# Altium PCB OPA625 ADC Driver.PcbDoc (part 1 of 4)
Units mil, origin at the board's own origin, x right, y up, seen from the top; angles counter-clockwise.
Board outline 4590 x 3930 mil, 4 copper layers (Layer 1 - Top Layer, Layer 2 - GND, Layer 3 - PWR, Layer 4 - Bottom Layer), stack 59.034 mil thick; 428 components, 236 nets, 1203 pads, 546 vias.
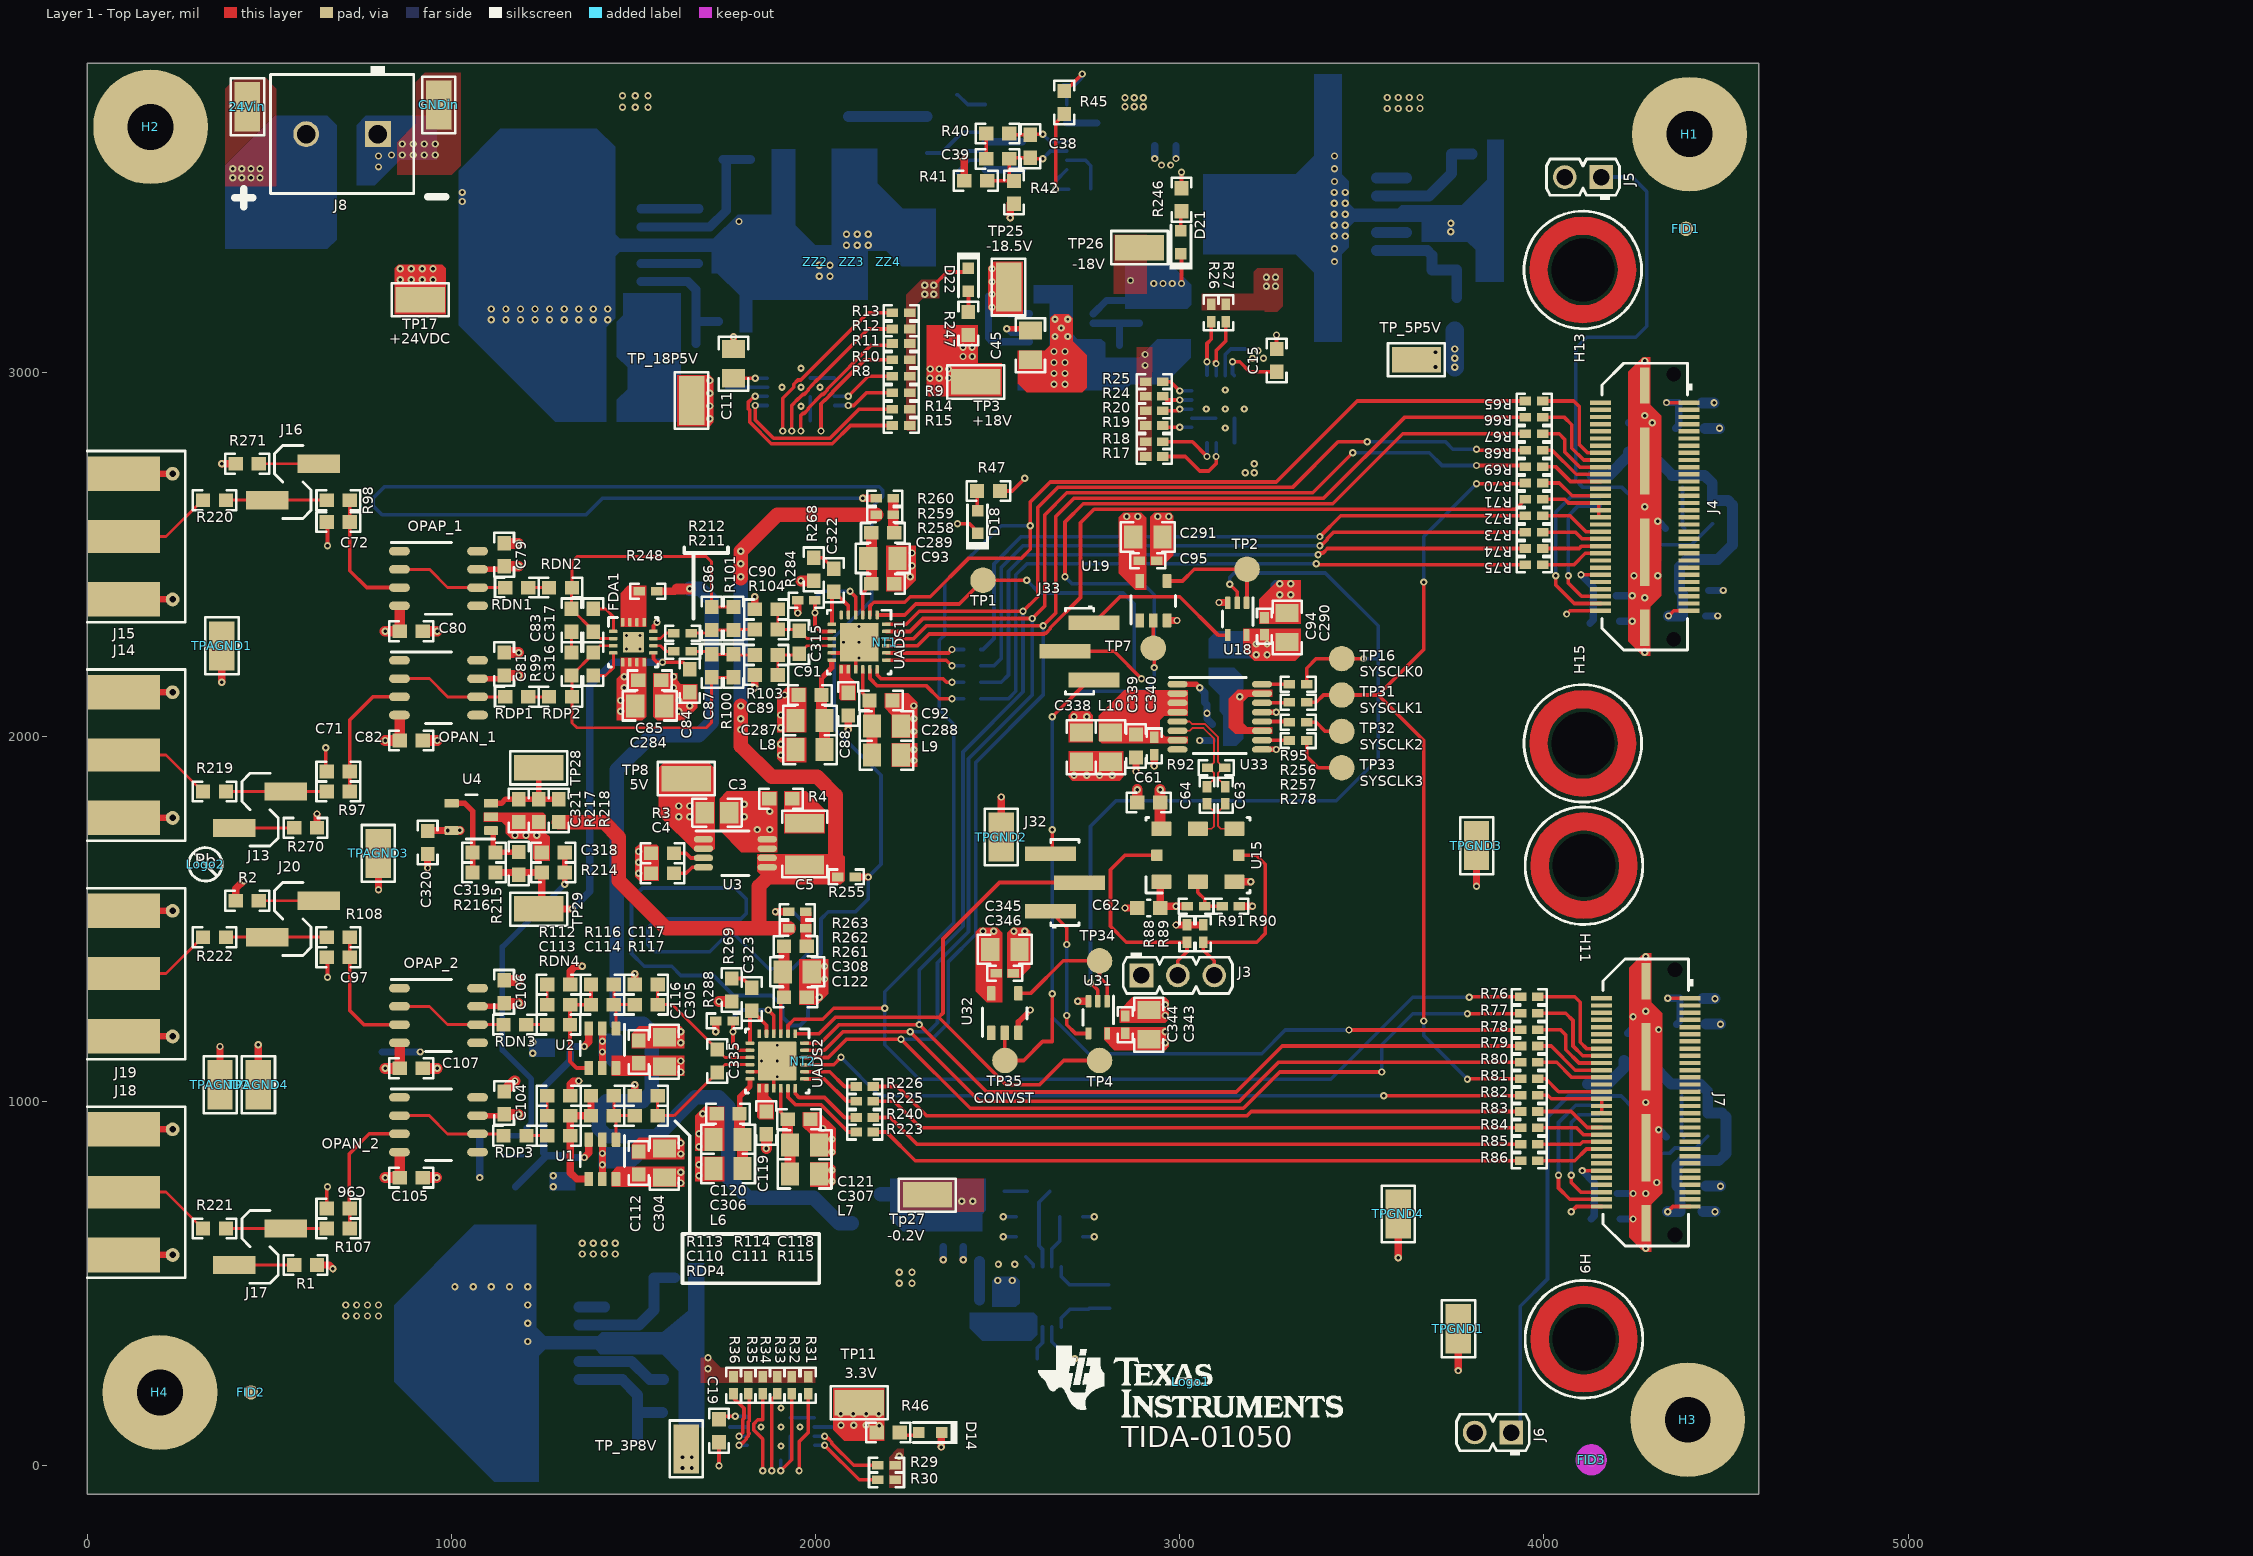
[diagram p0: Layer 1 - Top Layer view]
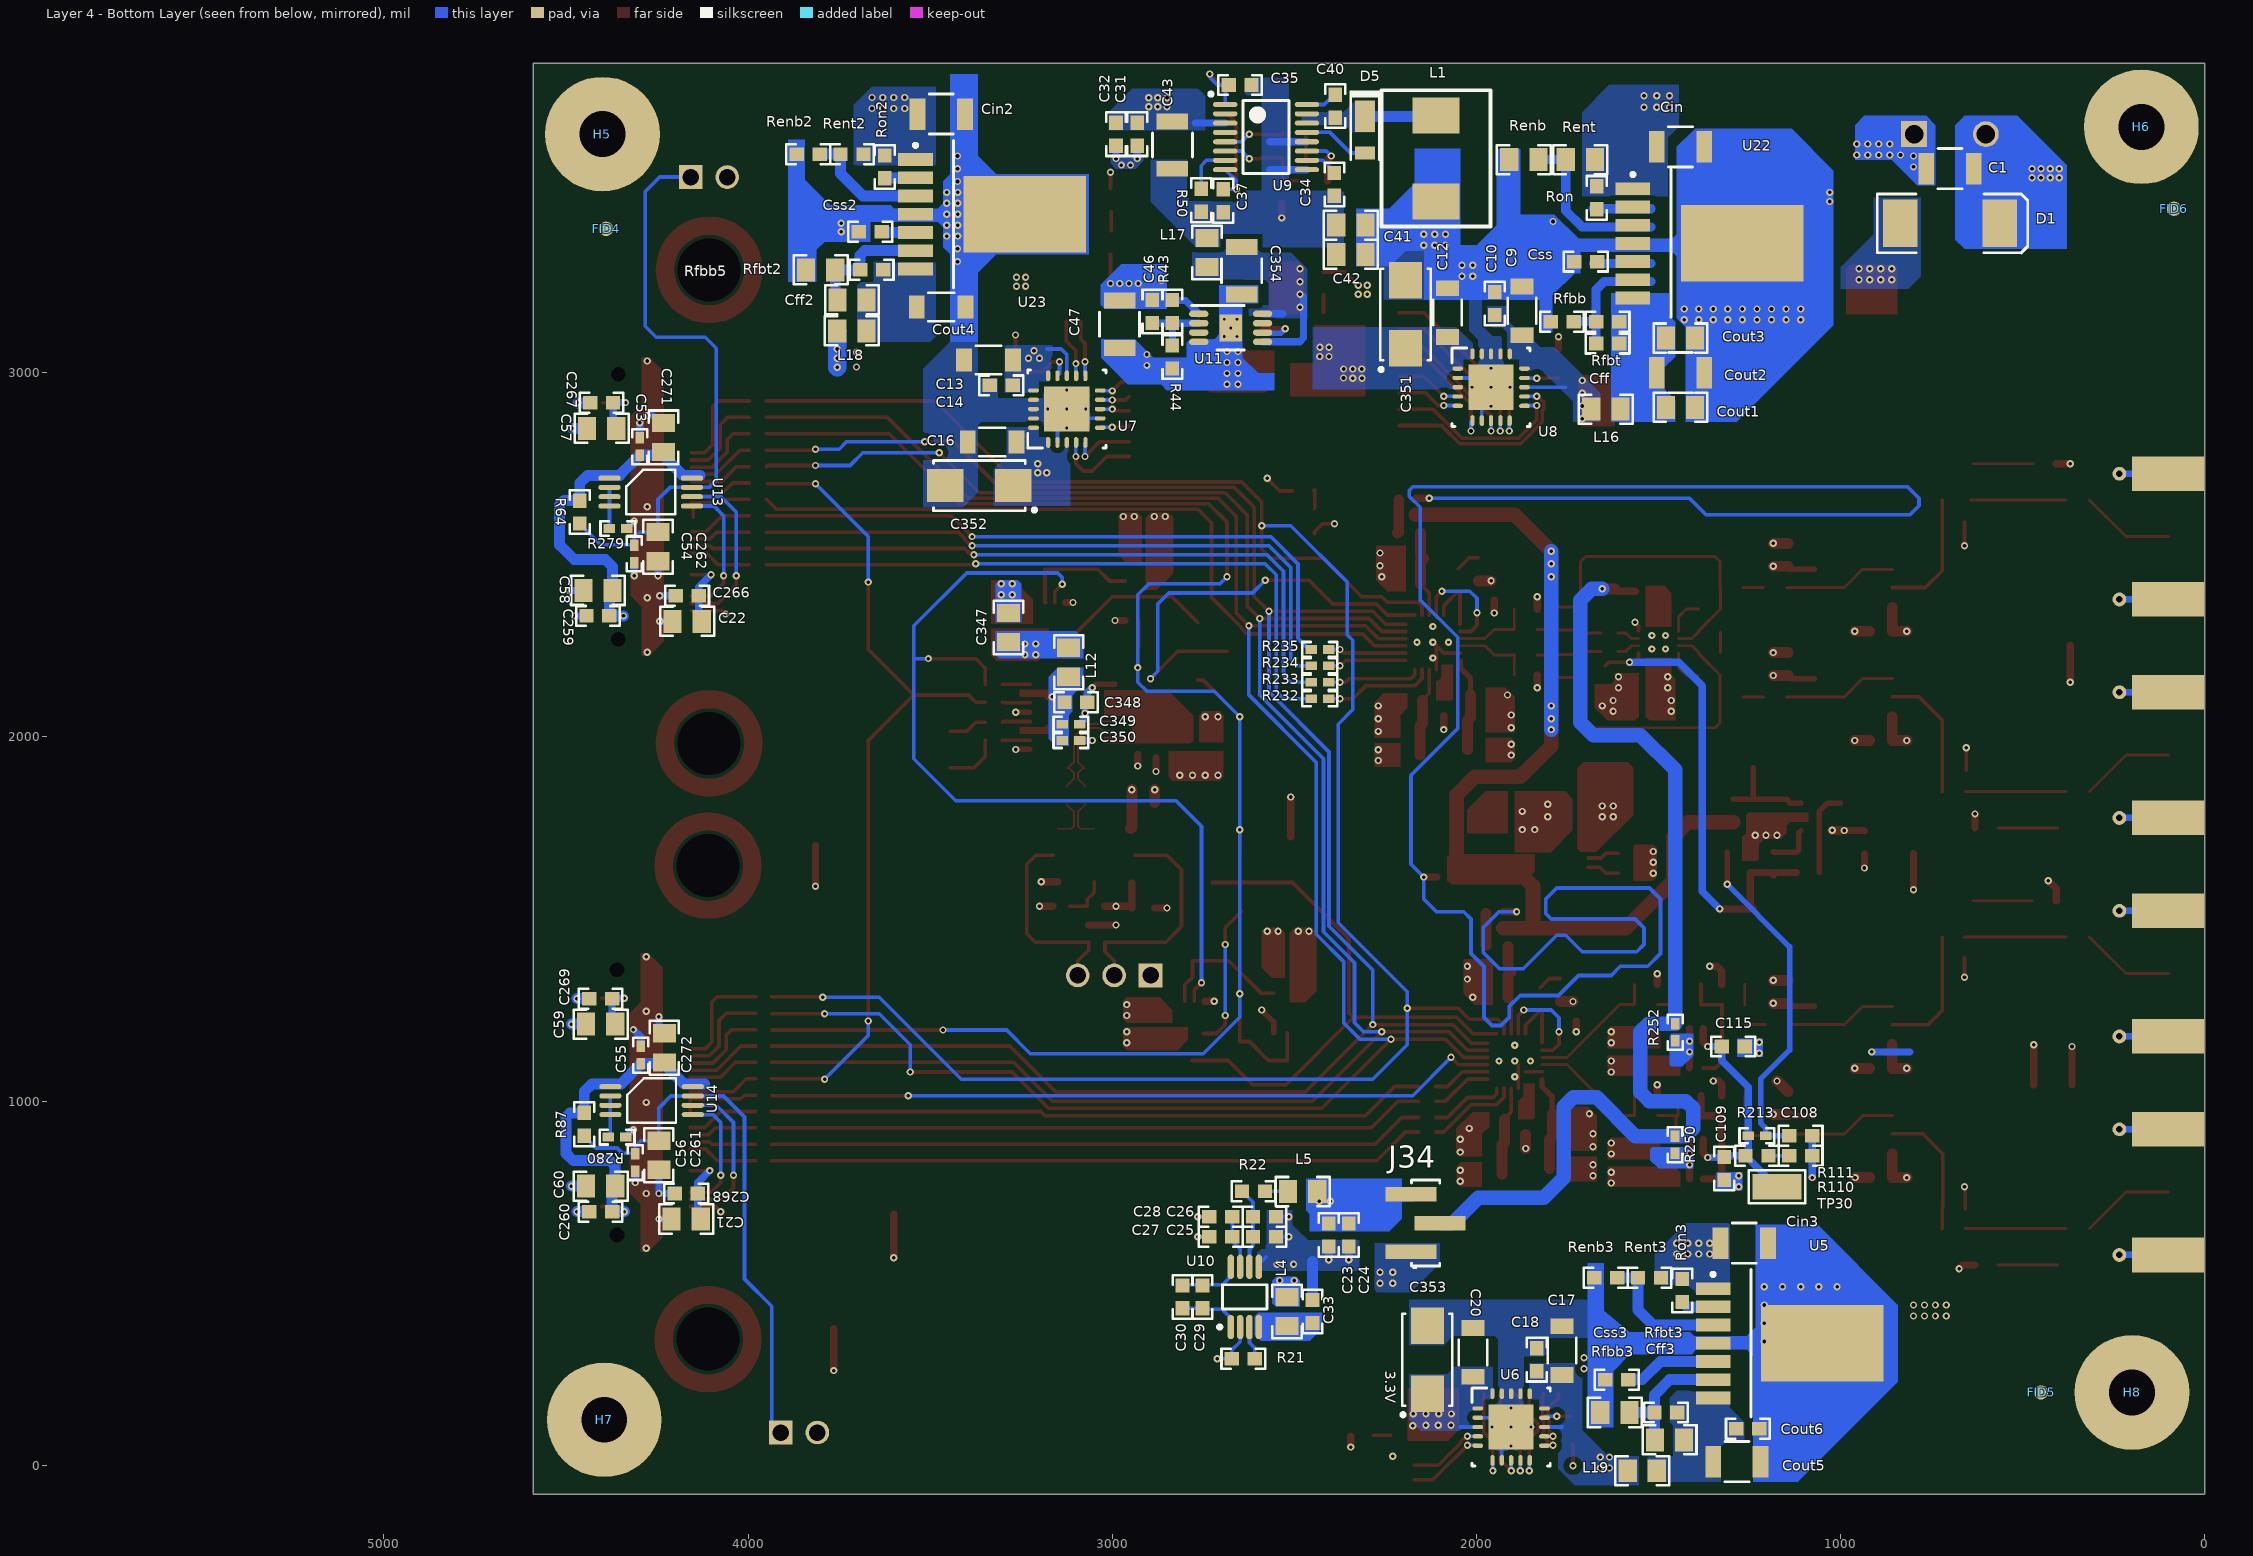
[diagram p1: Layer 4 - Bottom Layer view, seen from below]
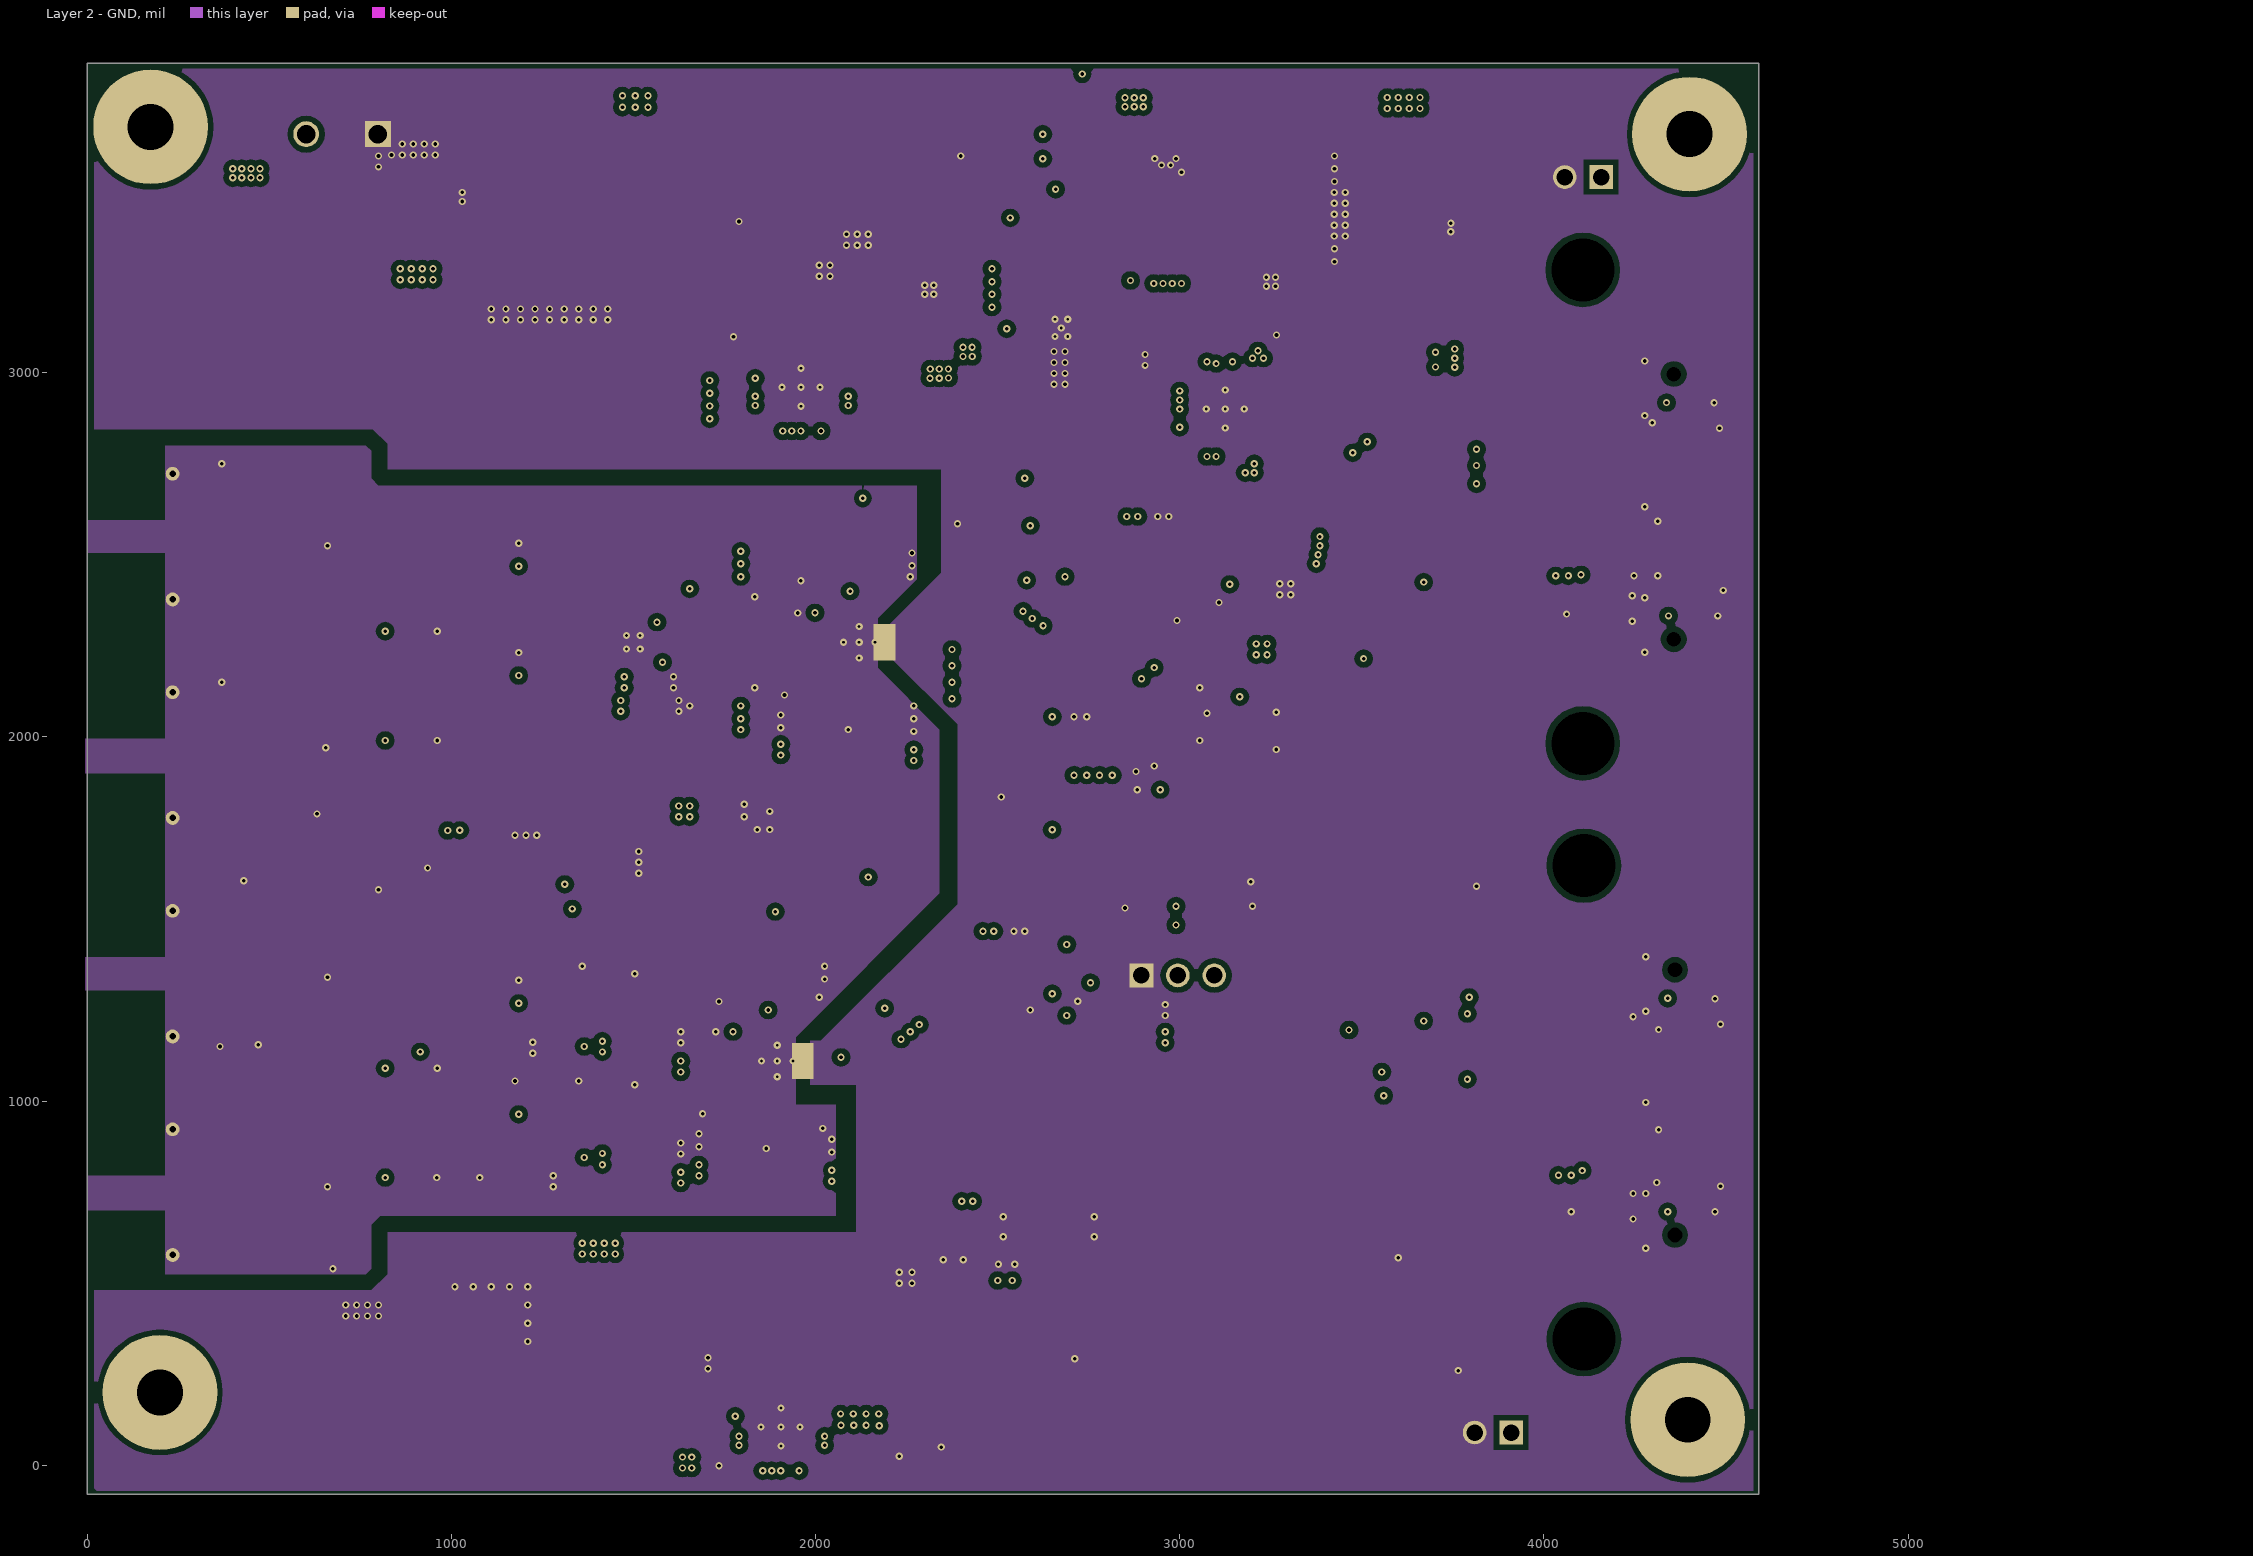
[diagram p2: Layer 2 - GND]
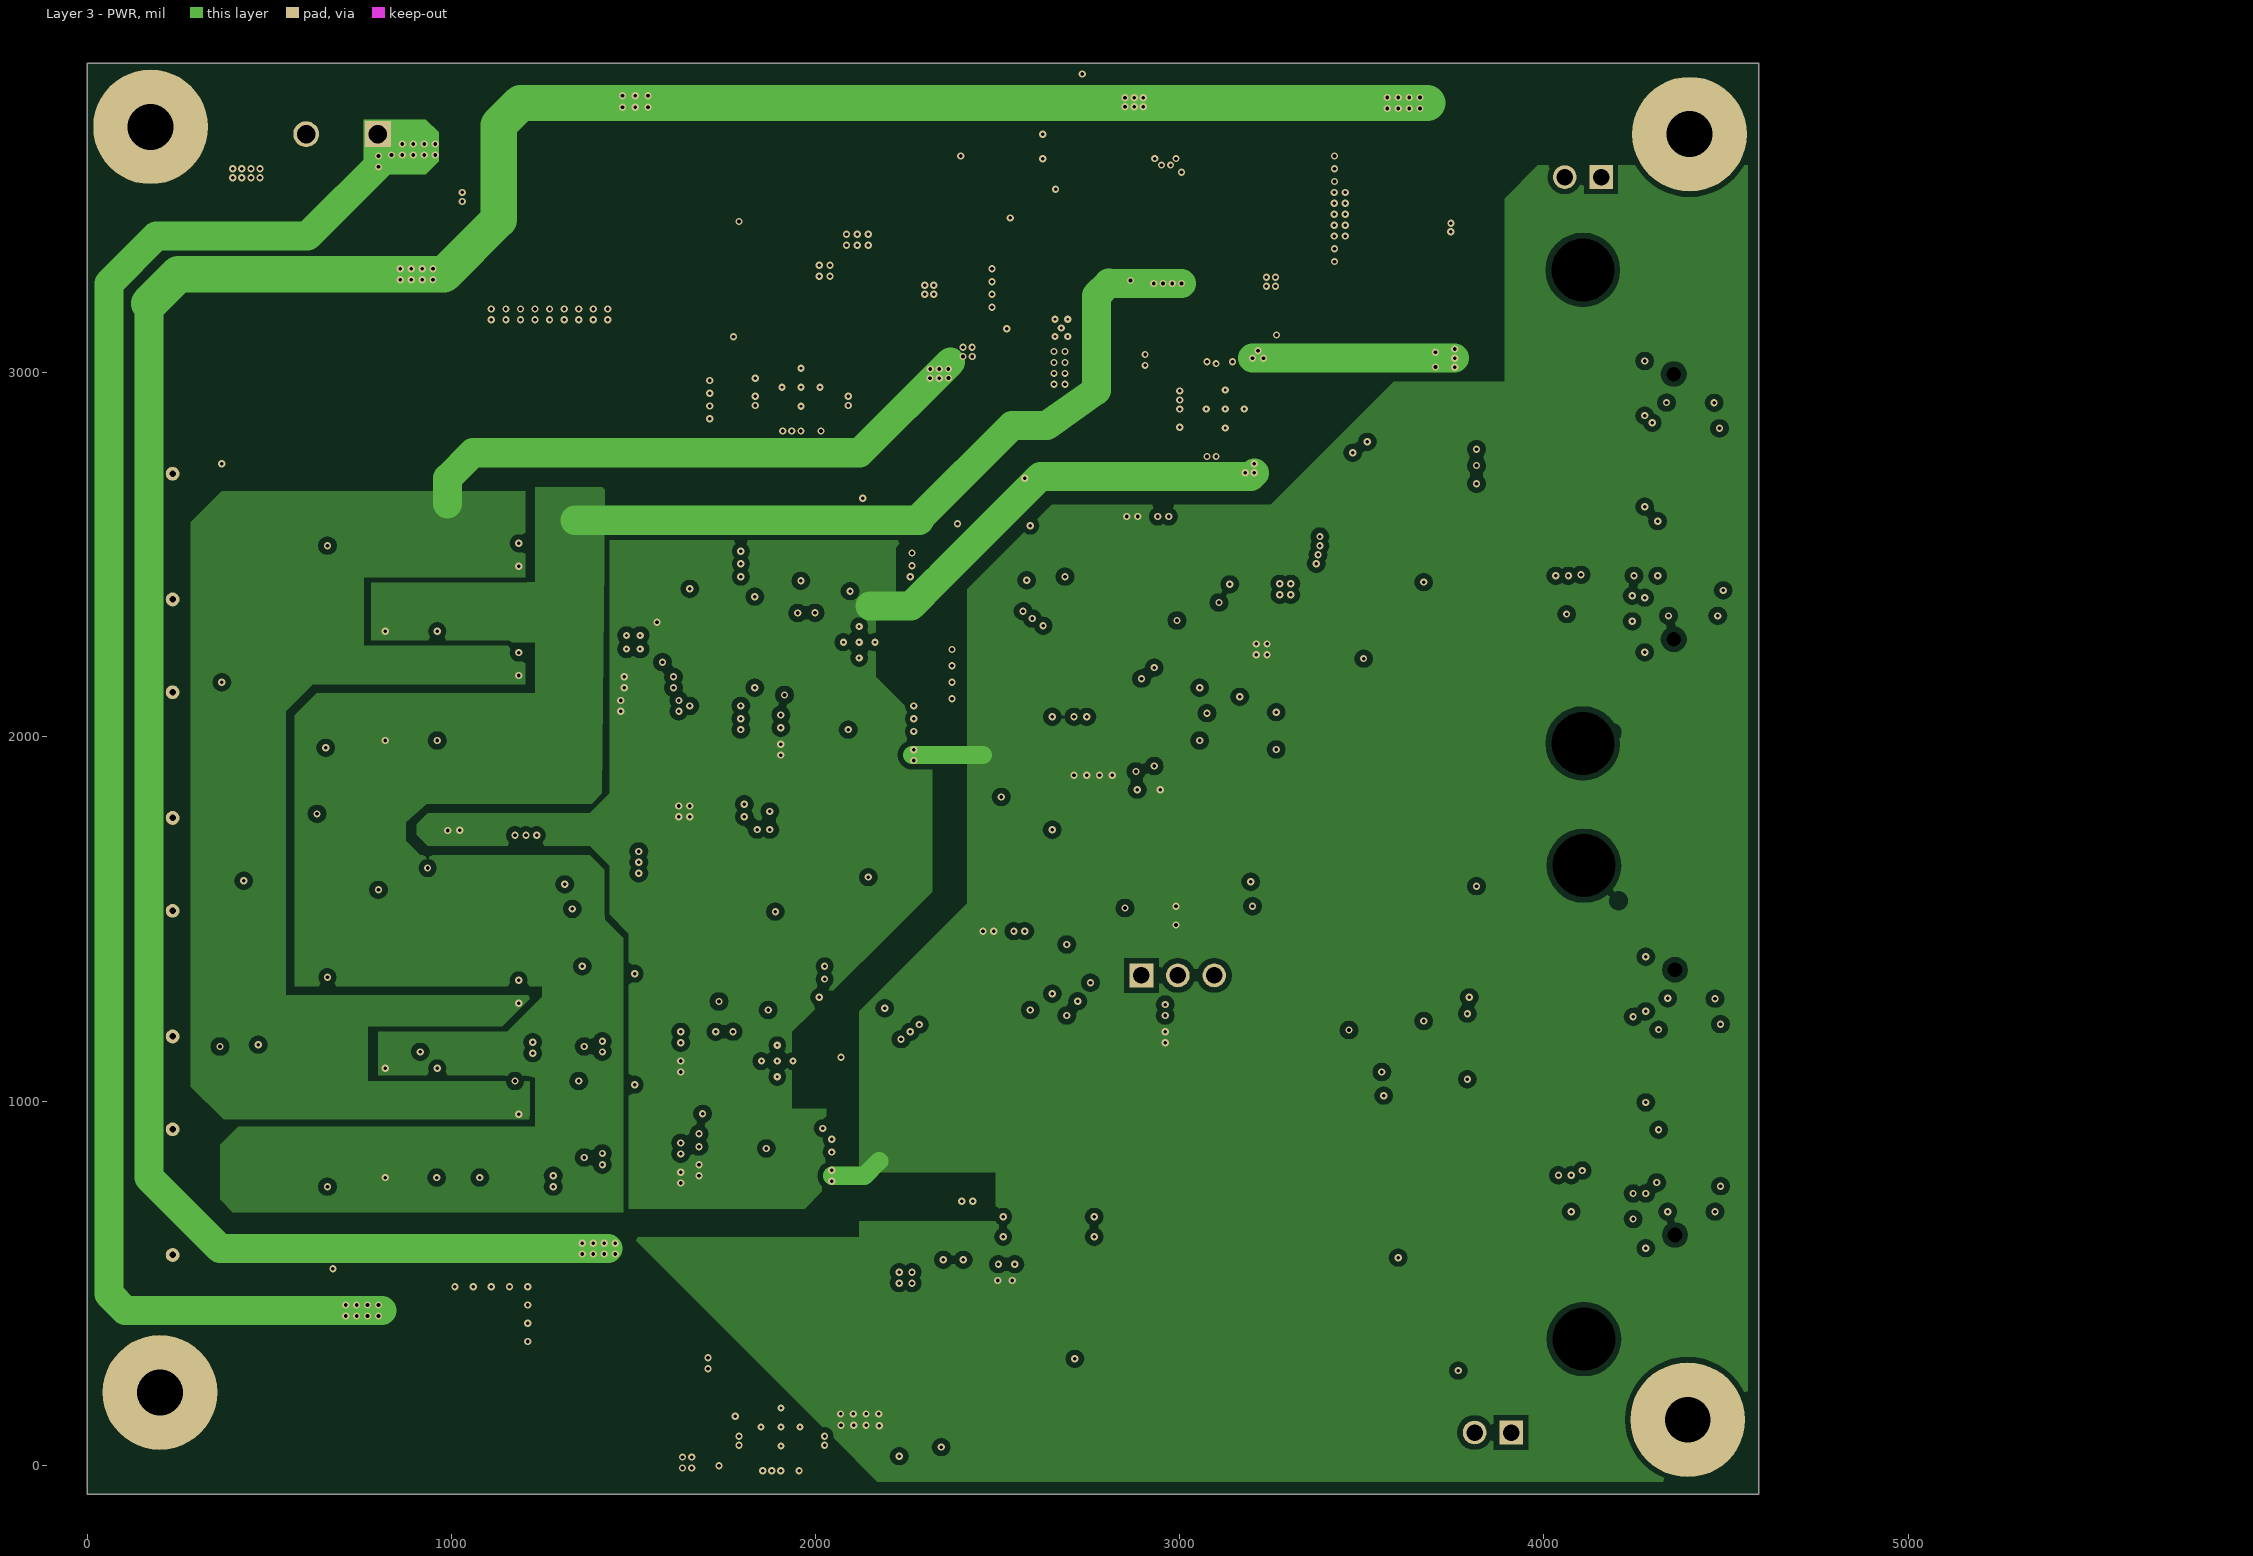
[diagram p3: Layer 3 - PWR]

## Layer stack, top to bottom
Top Solder: solder mask 0.4, Solder Resist, Dk 3.5
Layer 1 - Top Layer: signal copper 1.4
Dielectric 1: prepreg 5.2, 370HR, Dk 4.2
Layer 2 - GND: signal copper 1.417
Dielectric 2: core 43, 370HR, Dk 4.2
Layer 3 - PWR: signal copper 1.417
Dielectric 3: prepreg 5.2, 370HR, Dk 4.2
Layer 4 - Bottom Layer: signal copper 1.4
Bottom Solder: solder mask 0.4, Solder Resist, Dk 3.5

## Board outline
0,-80 0,3850 4590,3850 4590,-80

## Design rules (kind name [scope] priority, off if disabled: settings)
AcuteAngle [All] p1: minimum=4.50000000000000E+0001 checktracksonly=FALSE
AssemblyTestPointUsage [All] p1: valid=2
Clearance Clearance_Keepouts [((IsTrack Or IsArc) And Not InPoly) And IsFree and IsKeepOut vs ((IsTrack Or IsArc) And Not InPoly) And IsFree and IsKeepOut] p1: gap=0
Clearance Clearance_BoardEdge_MountingHoles [OnCopper and InComponentClass('Mounting Holes') vs IsKeepOut] p2: gap=40
Clearance Clearance_BoardEdge_Poly [OnCopper and InPoly vs IsKeepOut] p3: gap=25
Clearance Clearance_BoardEdge [OnCopper and Not InComponentClass('Logo') and not InComponentClass('FiducialMark') and not InRegion(1000,500,4000,800) and Not IsKeepout vs IsKeepOut] p4: gap=75
Clearance Clearance_Poly [InPolygon] p5: gap=15
Clearance [All] p6: gap=5
ComponentClearance ComponentClearance_MountingHoles_FiducialMarks [InComponentClass('Mounting Holes') vs InComponentClass('FiducialMark')] p1: gap=25 collisioncheckmode=3 verticalgap=10 showdistances=FALSE
ComponentClearance ComponentClearance_Shunt [InComponentClass('Header') vs InComponentClass('Shunt')] p2: gap=0 collisioncheckmode=3 verticalgap=0 showdistances=FALSE
ComponentClearance ComponentClearance_Logo [InComponentClass('Logo')] p3: gap=10 collisioncheckmode=3 verticalgap=10 showdistances=FALSE
ComponentClearance ComponentClearance_ScrewToNut [(HasFootprint('NY PMS 440 0025 PH')) vs (HasFootprint('Keystone_1902C'))] p4: gap=5 collisioncheckmode=3 verticalgap=10 showdistances=FALSE
ComponentClearance ComponentClearance_MountingHoles [InComponentClass('Mounting Holes')] p5: gap=15 collisioncheckmode=3 verticalgap=100000 showdistances=FALSE
ComponentClearance ComponentClearance_SmallPassives [HasFootprint('0201*') or HasFootprint('0402*') or HasFootprint('0508') or HasFootprint('0603*') or HasFootprint('0612') or HasFootprint('0805*') or HasFootprint('0815*') or HasFootprint('0830*') or HasFootprint('1206*') or HasFootprint('1210*') or HasFootprint('1808*') or HasFootprint('1812*') or HasFootprint('1825*') or HasFootprint('2010*') or HasFootprint('2220*') or HasFootprint('2225*') or HasFootprint('2512*') or HasFootprint('2728*') or HasFootprint('3518*') vs HasFootprint('0201*') or HasFootprint('0402*') or HasFootprint('0508') or HasFootprint('0603*') or HasFootprint('0612') or HasFootprint('0805*') or HasFootprint('0815*') or HasFootprint('0830*') or HasFootprint('1206*') or HasFootprint('1210*') or HasFootprint('1808*') or HasFootprint('1812*') or HasFootprint('1825*') or HasFootprint('2010*') or HasFootprint('2220*') or HasFootprint('2225*') or HasFootprint('2512*') or HasFootprint('2728*') or HasFootprint('3518*')] p6: gap=5 collisioncheckmode=3 verticalgap=10 showdistances=FALSE
ComponentClearance ComponentClearance_THtoSMT [IsThruComponent vs IsSMTComponent] p7: gap=10 collisioncheckmode=3 verticalgap=30 showdistances=FALSE
ComponentClearance ComponentClearance_THtoTH [IsThruComponent vs IsThruComponent] p8: gap=75 collisioncheckmode=3 verticalgap=30 showdistances=FALSE
ComponentClearance [All] p9: gap=5 collisioncheckmode=3 verticalgap=10 showdistances=FALSE
DiffPairsRouting [All] p1: maxlimit=20 minlimit=6 mostfreqgap=6 toplayer_minwidth=5 toplayer_maxwidth=5 toplayer_prefwidth=5 midlayer1_minwidth=5 midlayer1_maxwidth=5 midlayer1_prefwidth=5 midlayer2_minwidth=5 midlayer2_maxwidth=5 midlayer2_prefwidth=5 bottomlayer_minwidth=5 bottomlayer_maxwidth=5 bottomlayer_prefwidth=5 maxuncoupledlength=1000
FabricationTestPointUsage TestPointUsage [All] p1: valid=2 allowmultiple=FALSE
FabricationTestpoint Testpoint [All] p1: side=3 testpointundercomponent=TRUE minsize=40 maxsize=100 preferedsize=60 minholesize=0 maxholesize=40 preferedholesize=32 testpointgrid=1 allowsidetop=TRUE allowsidebottom=TRUE usegrid=TRUE gridtolerance=0.01
FanoutControl Fanout_LCC [IsLCC] p1: bgadir=Out bgaviamode=Centered fanoutstyle=Auto fanoutdirection=Alternating viagrid=1 // Fanout_LCC (Default Rule)
FanoutControl Fanout_BGA [IsBGA] p2: bgadir=Out bgaviamode=Centered fanoutstyle=Auto fanoutdirection=Alternating viagrid=1 // Fanout_BGA (Default Rule)
FanoutControl Fanout_Default [All] p4: bgadir=Out bgaviamode=Centered fanoutstyle=Auto fanoutdirection=Alternating viagrid=1 // Fanout_Default (Default Rule)
FanoutControl Fanout_Small [(CompPinCount < 5)] p5: bgadir=Out bgaviamode=Centered fanoutstyle=Auto fanoutdirection=OutThenIn viagrid=1 // Fanout_Small (Default Rule)
HoleSize [All] p1: absolutevalues=TRUE maxlimit=251 minlimit=6 maxpercent=80.000 minpercent=20.000
MinimumAnnularRing MinimumAnnularRing_ThermalPadVias [IsVia and InAnyComponent] p1: minimumring=5.91
MinimumAnnularRing [All] p2: minimumring=5
MinimumSolderMaskSliver MinimumSolderMaskSliver_Logo [InComponentClass('Logo') vs InComponentClass('Logo')] p1: minsoldermaskwidth=0.7
MinimumSolderMaskSliver [All] p2: minsoldermaskwidth=3.94
PlaneConnect [All] p1: planeconnectstyle=Relief reliefexpansion=10 reliefentries=4 reliefconductorwidth=10 reliefairgap=10
PolygonConnect [All] p1: connectstyle=Direct reliefconductorwidth=10 reliefentries=4 polygonreliefangle="90 Angle" airgapwidth=10
RoutingVias ThermalPadVias [IsVia and InAnyComponent] p1: holewidth=7.87 width=19.68 viastyle="Through Hole" minholewidth=7.87 minwidth=19.68 maxholewidth=12.99 maxwidth=23.62
RoutingVias [All] p2: holewidth=16 width=34 viastyle="Through Hole" minholewidth=7.87 minwidth=20 maxholewidth=40 maxwidth=65
SilkToBoardRegionClearance [Not ((IsComment or IsDesignator) And (Hide <> 'False')) and not InRegion(1000,500,4000,800)] p1:
SilkToSilkClearance SilkToSilkClearance_Pb-FreeLogo [(HasFootprint('Pb-Free_Overlay_Medium') OR HasFootprint('Pb-Free_Overlay_Small')) vs (HasFootprint('Pb-Free_Overlay_Medium') OR HasFootprint('Pb-Free_Overlay_Small'))] p1: silktosilkclearance=0
SilkToSilkClearance [All] p2: silktosilkclearance=4
SilkToSolderMaskClearance SilkToComonentPadClearance [IsPad and InAnycomponent] p1: minsilkscreentomaskgap=4 clearancetoexposedcopper=TRUE
SilkToSolderMaskClearance "Silk to Solder Mask Opening" [All] p2: minsilkscreentomaskgap=4 clearancetoexposedcopper=FALSE
SolderMaskExpansion [All] p1: expansion=1.97
Width [All] p1: maxlimit=100 minlimit=5 preferedwidth=10 checkconnectedcopper=TRUE
15 further rules are at their usual default settings.

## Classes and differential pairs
component class "OPA625 ADC Driver_Power": 24Vin C1 C9 C10 C11 C12 C13 C14 C15 C16 C17 C18 C19 C20 C23 C24 C25 C26 C27 C28 C29 C30 C31 C32 C33 C34 C35 C37 C38 C39 C40 C41 C42 C43 C45 C46 C47 C351 C352 C353 C354 Cff Cff2 Cff3 Cin Cin2 Cin3 Cout1 Cout2 Cout3 Cout4 Cout5 Cout6 Css Css2 Css3 D1 D5 D14 D18 D21 D22 GNDin J8 J34 L1 L4 L5 L16 L17 L18 L19 NT1 NT2 R8 R9 R10 R11 R12 R13 R14 R15 R17 R18 R19 R20 R21 R22 R24 R25 R26 R27 R29 R30 R31 R32 R33 R34 R35 R36 R40 R41 R42 R43 R44 R45 R46 R47 R50 R246 R247 Renb Renb2 Renb3 Rent Rent2 Rent3 Rfbb Rfbb3 Rfbb5 Rfbt Rfbt2 Rfbt3 Ron Ron2 Ron3 TP3 TP8 TP11 TP17 TP25 TP26 Tp27 TP_3P8V TP_5P5V TP_18P5V TPAGND1 TPAGND2 TPAGND3 TPAGND4 TPGND TPGND1 TPGND2 TPGND3 TPGND4 U5 U6 U7 U8 U9 U10 U11 U22 U23
component class "OPA625 ADC Driver_OPA625 ADC Driver": C3 C4 C5 C71 C72 C79 C80 C81 C82 C83 C84 C85 C86 C87 C88 C89 C90 C91 C92 C93 C94 C95 C96 C97 C104 C105 C106 C107 C108 C109 C110 C111 C112 C113 C114 C115 C116 C117 C118 C119 C120 C121 C122 C284 C287 C288 C289 C290 C291 C304 C305 C306 C307 C308 C315 C316 C317 C318 C319 C320 C321 C322 C323 C335 C343 C344 C345 C346 FDA1 J13 J14 J15 J16 J17 J18 J19 J20 J32 J33 L6 L7 L8 L9 OPAN_1 OPAN_2 OPAP_1 OPAP_2 R1 R2 R3 R4 R97 R98 R99 R100 R101 R103 R104 R107 R108 R110 R111 R112 R113 R114 R115 R116 R117 R211 R212 R213 R214 R215 R216 R217 R218 R219 R220 R221 R222 R223 R225 R226 R232 R233 R234 R235 R240 R248 R250 R252 R255 R258 R259 R260 R261 R262 R263 R268 R269 R270 R271 R284 R288 RDN1 RDN2 RDN3 RDN4 RDP1 RDP2 RDP3 RDP4 TP1 Tp2 TP4 TP7 TP28 TP29 TP30 TP34 TP35 U1 U2 U3 U4 U18 U19 U31 U32 UADS1 UADS2
component class "OPA625 ADC Driver_Connectors": C21 C22 C53 C54 C55 C56 C57 C58 C59 C60 C259 C260 C261 C262 C266 C267 C268 C269 C271 C272 J4 J5 J6 J7 R64 R65 R66 R67 R68 R69 R70 R71 R72 R73 R74 R75 R76 R77 R78 R79 R80 R81 R82 R83 R84 R85 R86 R87 R279 R280 U13 U14
component class "OPA625 ADC Driver_Clock": C61 C62 C63 C64 C338 C339 C340 C347 C348 C349 C350 J3 L10 L12 R88 R89 R90 R91 R92 R95 R256 R257 R278 TP16 TP31 TP32 TP33 U15 U33
component class Header: J3 J5 J6 J13 J16 J17 J20 J32 J33 J34
component class "Mounting Holes": H1 H2 H3 H4
component class Logo: Logo1
component class "OPA625 ADC Driver_Hardware": FID1 FID2 FID3 FID4 FID5 FID6 H1 H2 H3 H4 H5 H6 H7 H8 H9 H11 H13 H15 Logo1 Logo2 ZZ2 ZZ3 ZZ4
component class FiducialMark: FID1 FID2 FID3 FID4 FID5 FID6
component class AssemblyNote: ZZ2 ZZ3 ZZ4
differential pair BCLK1: +BCLK1_P -BCLK1_N
differential pair BCLK0: +BCLK0_P -BCLK0_N

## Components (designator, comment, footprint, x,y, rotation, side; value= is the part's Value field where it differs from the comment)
24Vin "5015" Testpoint_Keystone_Miniature 440,3730 r90 top
C1 "UMK325AB7106KM-T" 1210_280 700,3560 r0 bottom
C3 "GRM21BR71A106KE51L" 0805 1729.79,1791.91 r180 top
C4 "GRM188R71A105KA61D" 0603 1580,1625.41 r180 top
C5 "GRM32ER71A476KE15L" 1210_270 1970,1705.41 r90 top
C9 "C3216X5R1E476M160AC" 1206_190 1875,3170 r90 bottom
C10 "CGA3E2X7R2A102K080AA" 0603 1950,3190 r90 bottom
C11 "C2012X7S2A105K125AB" 0805_HV 1775,3025 r90 top
C12 "C3216X5R1E476M160AC" 1206_190 2080,3165 r90 bottom
C13 "C3216X5R1E476M160AC" 1206_190 3340,3035 r0 bottom
C14 "GRM1885C1H102FA01J" 0603 3305,2965 r0 bottom
C15 "GRM188R71E105KA12D" 0603 3266.02,3033.66 r270 top
C16 "C3216X5R1E476M160AC" 1206_190 3330,2810 r0 bottom
C17 "C3216X5R1E476M160AC" 1206_190 1765,315 r90 bottom
C18 "GRM1885C1H102FA01J" 0603 1835,290 r90 bottom
C19 "GRM188R71E105KA12D" 0603 1735,95 r90 top
C20 "C3216X5R1E476M160AC" 1206_190 2010,310 r90 bottom
C21 "GRM21BR71A106KE51L" 0805_HV 4169.99,676.32 r0 bottom
C22 "GRM21BR71A106KE51L" 0805_HV 4167.34,2317.19 r0 bottom
C23 "GRM188R61A106ME69D" 0603 2406.02,632.23 r270 bottom
C24 "GRM188R61A106ME69D" 0603 2351.02,632.23 r270 bottom
C25 "GRM188R71E474KA12D" 0603 2582.25,627.23 r180 bottom
C26 "GRM188R60J226MEA0D" 0603 2582.25,682.23 r180 bottom
C27 "GRM188R61C104KA01D" 0603 2702.25,627.23 r0 bottom
C28 "GRM188R60J226MEA0D" 0603 2702.25,682.23 r0 bottom
C29 "GRM188R61A475MAAJ" 0603 2752.25,462.23 r90 bottom
C30 "GRM188R61A224KA01D" 0603 2807.25,462.23 r90 bottom
C31 "GCM188R71H224KA64D" 0603 2931.46,3655 r270 bottom
C32 "C1608X7R1H104K080AA" 0603 2990,3655 r270 bottom
C33 "GRM188R61A106ME69D" 0603 2450.2,422.23 r90 bottom
C34 "GRM188R71H333KA61D" 0603 2390.15,3516.89 r270 bottom
C35 "C1608X7R1H104K080AA" 0603 2649.25,3789.94 r180 bottom
C37 "C0603C911J5GACTU" 0603 2695.15,3471.89 r270 bottom
C38 "CGA3E2C0G1H100D080AA" 0603 2590.15,3621.89 r90 top
C39 "GRM1885C1H151JA01D" 0603 2500.15,3586.89 r180 top
C40 "GRM188R71H223KA01D" 0603 2387.87,3731.89 r90 bottom
C41 "C2012X5R1V226M125AC" 0805_HV 2345,3405 r0 bottom
C42 "C2012X7S2A105K125AB" 0805_HV 2345,3325 r0 bottom
C43 "UMK325AB7106KM-T" 1210_280 2835,3625 r270 bottom
C45 "C2012X7S2A105K125AB" 0805_HV 2590.21,3075.7 r270 top
C46 "GCM188R71H103KA37D" 0603 2890,3168.05 r270 bottom
C47 "UMK325AB7106KM-T" 1210_280 2980,3133.05 r270 bottom
C53 "GRM155R71C104KA88D" 0402 4297.34,2797.19 r270 bottom
C54 "GRM155R71C104KA88D" 0402 4312.34,2502.19 r90 bottom
C55 "GRM155R71C104KA88D" 0402 4294.99,1126.32 r270 bottom
C56 "GRM155R71C104KA88D" 0402 4310,831.32 r90 bottom
C57 "GRM21BR71A106KE51L" 0805_HV 4402.34,2847.19 r0 bottom
C58 "GRM21BR71A106KE51L" 0805_HV 4412.34,2402.19 r0 bottom
C59 "GRM21BR71A106KE51L" 0805_HV 4405,1211.32 r0 bottom
C60 "GRM21BR71A106KE51L" 0805_HV 4405,766.32 r0 bottom
C61 "C0603C104J3RACTU" 0603 2915,1820 r180 top
C62 "ZRB18AD71A106KE01L" 0603_120 2915,1530 r180 top
C63 "GRM155R61E104KA87D" 0402 3125,1840 r90 top
C64 "GRM155R61E104KA87D" 0402 3075,1840 r90 top
C71 "GRM1885C1H101JA01D" 0603 690,1905 r0 top
C72 "GRM1885C1H101JA01D" 0603 690,2590 r0 top
C79 "GRM188R72A104KA35D" 0603 1145,2500 r270 top
C80 "GRM188R72A104KA35D" 0603 890,2290 r180 top
C81 "GRM188R72A104KA35D" 0603 1145,2200 r270 top
C82 "GRM188R72A104KA35D" 0603 889.99,1990 r180 top
C83 "C0603C680J5GACTU" 0603 1330,2320 r90 top
C84 "C0603C104J3RACTU" 0603 1655,2154 r270 top
C85 "C0603C104J3RACTU" 0603 1545,2155 r0 top
C86 "C0603C270J5GACTU" 0603 1715,2325 r90 top
C87 "C0603C270J5GACTU" 0603 1715,2195 r270 top
C88 "GRM188R71A105KA61D" 0603 2090,2090 r90 top
C89 "C1608C0G2A102J080AA" 0603 1865,2170 r180 top
C90 "C1608C0G2A102J080AA" 0603 1865,2350 r180 top
C91 "C0603C104J3RACTU" 0603 1985,2115 r0 top
C92 "C0603C104J3RACTU" 0603 2180,2100 r0 top
C93 "C0603C104J3RACTU" 0603 2185,2420 r0 top
C94 "GRM155R71C104KA88D" 0402 3232.81,2303.8 r270 top
C95 "GRM155R71C104KA88D" 0402 2912.81,2483.8 r180 top
C96 "GRM1885C1H101JA01D" 0603 690,705 r0 top
C97 "GRM1885C1H101JA01D" 0603 690,1395 r0 top
C104 "GRM188R72A104KA35D" 0603 1145,995 r270 top
C105 "GRM188R72A104KA35D" 0603 890,790 r180 top
C106 "GRM188R72A104KA35D" 0603 1145,1300 r270 top
C107 "GRM188R72A104KA35D" 0603 890,1090 r180 top
C108 "C0603C104J3RACTU" 0603 1110,905 r180 bottom
C109 "C0603C102J5GAC" 0603 1320,815 r270 bottom
C110 "C0603C471K5RACTU" 0603 1295,960 r0 top
C111 "C0603C101J5GAC" 0603 1415,960 r180 top
C112 "C0603C104J3RACTU" 0603 1515,830 r270 top
C113 "C0603C471K5RACTU" 0603 1295,1265 r180 top
C114 "C0603C101J5GAC" 0603 1415,1265 r180 top
C115 "C0603C102J5GAC" 0603 1295,1150 r180 bottom
C116 "C0603C104J3RACTU" 0603 1515,1135 r270 top
C117 "C1608C0G2A102J080AA" 0603 1535,1320 r180 top
C118 "C1608C0G2A102J080AA" 0603 1535,1015 r180 top
C119 "GRM188R71A105KA61D" 0603 1865,940 r270 top
C120 "C0603C104J3RACTU" 0603 1760,965 r0 top
C121 "C0603C104J3RACTU" 0603 1955,950 r0 top
C122 "C0603C104J3RACTU" 0603 1945,1285 r0 top
C259 "C0603C104J3RACTU" 0603 4412.34,2332.19 r0 bottom
C260 "C0603C104J3RACTU" 0603 4405,696.32 r0 bottom
C261 "GRM21BR71A106KE51L" 0805_HV 4244.99,851.32 r270 bottom
C262 "GRM21BR71A106KE51L" 0805_HV 4247.34,2522.19 r270 bottom
C266 "C0603C104J3RACTU" 0603 4167.34,2387.19 r0 bottom
C267 "C0603C104J3RACTU" 0603 4402.34,2917.19 r0 bottom
C268 "C0603C104J3RACTU" 0603 4169.99,746.32 r0 bottom
C269 "C0603C104J3RACTU" 0603 4405,1281.33 r0 bottom
C271 "GRM21BR71A106KE51L" 0805_HV 4232.34,2822.19 r90 bottom
C272 "GRM21BR71A106KE51L" 0805_HV 4229.99,1146.32 r90 bottom
C284 "GRM21BR71A106KE51L" 0805_HV 1545,2085 r0 top
C287 "GRM21BR71A106KE51L" 0805_HV 1985,2045 r180 top
C288 "GRM21BR71A106KE51L" 0805_HV 2195,2030 r0 top
C289 "GRM21BR71A106KE51L" 0805_HV 2185,2490 r0 top
C290 "GRM21BR71A106KE51L" 0805_HV 3295,2300.3 r90 top
C291 "GRM21BR71A106KE51L" 0805_HV 2912.81,2548.8 r180 top
C304 "GRM21BR71A106KE51L" 0805_HV 1585,830 r90 top
C305 "GRM21BR71A106KE51L" 0805_HV 1585,1135 r90 top
C306 "GRM21BR71A106KE51L" 0805_HV 1760,895 r180 top
C307 "GRM21BR71A106KE51L" 0805_HV 1970,880 r0 top
C308 "GRM21BR71A106KE51L" 0805_HV 1950,1355 r0 top
C315 "CGA3E2C0G1H103J080AA" 0603 1955,2260 r90 top
C316 "C0603C104J3RACTU" 0603 1390,2200 r90 top
C317 "C0603C104J3RACTU" 0603 1390,2320 r270 top
C318 "GRM188R71E105KA12D" 0603 1280,1682.63 r180 top
C319 "GRM188R71E105KA12D" 0603 1090,1682.63 r180 top
C320 "C0603C104J3RACTU" 0603 935,1710 r90 top
C321 "GRM188R71E105KA12D" 0603 1185,1797.63 r270 top
C322 "C1608X5R1A226M080AC" 0603 2050,2430 r90 top
C323 "C1608X5R1A226M080AC" 0603 1825,1280 r90 top
C335 "CGA3E2C0G1H103J080AA" 0603 1730,1110 r90 top
C338 "GRM21BR71A106KE51L" 0805_HV 2730,1971.91 r90 top
C339 "GRM188R71E105KA12D" 0603 2880,1975 r270 top
C340 "GRM155R71C104KA88D" 0402 2930,1975 r270 top
C343 "GRM21BR71A106KE51L" 0805_HV 2915.21,1210 r90 top
C344 "GRM155R71C104KA88D" 0402 2850.21,1210 r270 top
C345 "GRM21BR71A106KE51L" 0805_HV 2519.83,1416.53 r180 top
C346 "GRM155R71C104KA88D" 0402 2519.83,1351.53 r180 top
C347 "GRM21BR71A106KE51L" 0805_HV 3285,2300.3 r90 bottom
C348 "GRM188R71E105KA12D" 0603 3100,2095 r180 bottom
C349 "GRM155R71C104KA88D" 0402 3113.55,2035 r180 bottom
C350 "GRM155R71C104KA88D" 0402 3113.55,1990 r180 bottom
C351 "293D475X9025C2TE3" 6032-28 2195,3160 r90 bottom
C352 "293D475X9025C2TE3" 6032-28 3365,2690 r0 bottom
C353 "293D475X9025C2TE3" 6032-28 2135,290 r90 bottom
C354 "UMK325AB7106KM-T" 1210_280 2645,3280 r270 bottom
Cff "C1608X7R2A223K080AA" 0603 1640,3080 r0 bottom
Cff2 "08055C223KAT2A" 0805_HV 3714.76,3200 r0 bottom
Cff3 "08055C223KAT2A" 0805_HV 1470,70 r0 bottom
Cin "UMK325AB7106KM-T" 1210_280 1440,3620 r180 bottom
Cin2 "UMK325AB7106KM-T" 1210_280 3469.76,3710 r180 bottom
Cin3 "UMK325AB7106KM-T" 1210_280 1265,610 r180 bottom
Cout1 "C2012JB1V226M125AC" 0805_HV 1440,2905 r180 bottom
Cout2 "UMK325AB7106KM-T" 1210_280 1440,3000 r180 bottom
Cout3 "C2012X7S2A105K125AB" 0805_HV 1440,3095 r180 bottom
Cout4 "C3216X5R1E476M160AC" 1206_190 3469.76,3180 r180 bottom
Cout5 "C3225X6S0J107M250AC" 1210_280 1285,10 r180 bottom
Cout6 "C0603C105K3RACTU" 0603 1255,100 r180 bottom
Css "CGA3E2X7R2A472K080AA" 0603 1700,3305 r180 bottom
Css2 "GRM188R70J103KA01D" 0603 3664.76,3387 r0 bottom
Css3 "GRM188R70J103KA01D" 0603 1615,235.07 r0 bottom
D1 "MBRS4201T3G" SMC 700,3410 r0 bottom
D5 "DFLS1100-7" PowerDI123 2306.17,3653.35 r270 bottom
D14 "150060RS75000" WL-SMCW_RED 2315,90 r180 top
D18 "150060RS75000" WL-SMCW_RED 2445,2590 r90 top
D21 "150060RS75000" WL-SMCW_RED 3003.32,3358.24 r90 top
D22 "150060RS75000" WL-SMCW_RED 2420,3255 r270 top
FDA1 "THS4551IRGTR" RGT0016A 1500,2260 r0 top
FID1 "Fiducial" Fiducial10-20#1 4390,3395 r90 top
FID2 "Fiducial" Fiducial10-20#1 450,200 r0 top
FID3 "Fiducial" Fiducial10-20#2 4130,15 r90 top
FID4 "Fiducial" Fiducial10-20#1 4390,3395 r270 bottom
FID5 "Fiducial" Fiducial10-20#1 450,200 r180 bottom
FID6 "Fiducial" Fiducial10-20#1 85,3450 r180 bottom
GNDin "5015" Testpoint_Keystone_Miniature 965,3735 r90 top
H1 "NY PMS 440 0025 PH" "NY PMS 440 0025 PH" 4400,3655 r0 top locked
H2 "NY PMS 440 0025 PH" "NY PMS 440 0025 PH" 174.47,3675 r0 top locked
H3 "NY PMS 440 0025 PH" "NY PMS 440 0025 PH" 4395,125 r0 top locked
H4 "NY PMS 440 0025 PH" "NY PMS 440 0025 PH" 200,200 r0 top locked
H5 "1902C" Keystone_1902C 4400,3655 r180 bottom locked
H6 "1902C" Keystone_1902C 174.47,3675 r180 bottom locked
H7 "1902C" Keystone_1902C 4395,125 r180 bottom locked
H8 "1902C" Keystone_1902C 200,200 r180 bottom locked
H9 "9774050360R" Wurth_WA-SMSI 4110,346.32 r180 top
H11 "9774050360R" Wurth_WA-SMSI 4110,1646.32 r180 top
H13 "9774050360R" Wurth_WA-SMSI 4106.85,3282.18 r180 top
H15 "9774050360R" Wurth_WA-SMSI 4106.85,1982.18 r180 top
J3 "61300311121" WURTH_61300311121 2995,1345 r0 top
J4 "QTH-030-01-L-D-A" Samtec_QTH-030-01-x-D-A 4276.85,2632.18 r270 top
J5 "61300211121" WURTH_61300211121 4107.34,3537.19 r180 top
J6 "61300211121" WURTH_61300211121 3860,90 r180 top
J7 "QTH-030-01-L-D-A" Samtec_QTH-030-01-x-D-A 4280,996.32 r270 top
J8 "691213710002" Wurth_691213710002 700,3655 r180 top
J13 "87898-0204" Molex_87898-0204 475,1800 r90 top
J14 "142-0701-801" JOHNSON_142-0701-801 100,1950 r90 top
J15 "142-0701-801" JOHNSON_142-0701-801 100,2550 r90 top
J16 "87898-0204" Molex_87898-0204 565,2700 r270 top
J17 "87898-0204" Molex_87898-0204 475,600 r90 top
J18 "142-0701-801" JOHNSON_142-0701-801 100,750 r90 top
J19 "142-0701-801" JOHNSON_142-0701-801 100,1350 r90 top
J20 "87898-0204" Molex_87898-0204 565,1500 r270 top
J32 "TMM-103-01-G-S-SM" Samtec_TMM-103-01-x-S-SM 2685,1600 r90 top
J33 "TMM-103-01-G-S-SM" Samtec_TMM-103-01-x-S-SM 2725,2235 r270 top
J34 "TMM-103-01-G-S-SM" Samtec_TMM-103-01-x-S-SM 2140,665 r90 bottom
L1 "DR73-331-R" DR73 2111.17,3588.35 r270 bottom
L4 "MPZ2012S601A" 0805_HV 2520.27,422.23 r90 bottom
L5 "MPZ2012S601A" 0805_HV 2477.25,751.57 r0 bottom
L6 "MPZ2012S601A" 0805_HV 1760,815 r0 top
L7 "MPZ2012S601A" 0805_HV 1970,800 r180 top
L8 "MPZ2012S601A" 0805_HV 1985,1965 r0 top
L9 "MPZ2012S601A" 0805_HV 2195,1950 r180 top
L10 "MPZ2012S601A" 0805_HV 2810,1971.91 r270 top
L12 "MPZ2012S601A" 0805_HV 3120,2205 r90 bottom
L16 "MPZ2012S601A" 0805_HV 1645,2900 r180 bottom
L17 "MPZ2012S601A" 0805_HV 2740,3330 r90 bottom
L18 "MPZ2012S601A" 0805_HV 3715,3115 r0 bottom
L19 "MPZ2012S601A" 0805_HV 1545,-15 r0 bottom
Logo1 "Texas Instruments" TI_Stacked_Overlay_Small 3030,230 r0 top
Logo2 "Pb-Free Symbol" Pb-Free_Overlay_Small 325,1650 r0 top
NT1 "Net-Tie" Net-Tie_50milWide_30milLong 2190,2260 r0 top net-tie
NT2 "Net-Tie" Net-Tie_50milWide_30milLong 1965,1110 r0 top net-tie
OPAN_1 "OPA827AIDR" D0008A_N 964.99,2135 r0 top
OPAN_2 "OPA827AIDR" D0008A_N 965,935 r0 top
OPAP_1 "OPA827AIDR" D0008A_N 965,2435 r0 top
OPAP_2 "OPA827AIDR" D0008A_N 965,1235 r0 top
R1 "RG1608P-102-B-T5" 0603 600,550 r0 top
R2 "RG1608P-102-B-T5" 0603 440,1550 r180 top
R3 "ERJ-3RQFR22V" 0603 1580,1680.41 r0 top
R4 "ERJ-3RQFR22V" 0603 1905,1830.41 r180 top
R8 "ERJ-2GE0R00X" 0402 2235,2990 r180 top
R9 "ERJ-2GE0R00X" 0402 2235,2945 r180 top
R10 "ERJ-2GE0R00X" 0402 2235,3035.98 r180 top
R11 "ERJ-2GE0R00X" 0402 2235,3080 r180 top
R12 "ERJ-2GE0R00X" 0402 2235,3120 r180 top
R13 "ERJ-2GE0R00X" 0402 2235,3165 r180 top
R14 "ERJ-2GE0R00X" 0402 2235,2900 r180 top
R15 "ERJ-2GE0R00X" 0402 2235,2855 r180 top
R17 "ERJ-2GE0R00X" 0402 2930,2770 r0 top
R18 "ERJ-2GE0R00X" 0402 2930,2810 r0 top
R19 "ERJ-2GE0R00X" 0402 2930,2855 r0 top
R20 "ERJ-2GE0R00X" 0402 2930,2895 r0 top
R21 "CRCW06030000Z0EA" 0603 2640.27,292.23 r180 bottom
R22 "RT0603DRE074R7L" 0603 2612.25,752.23 r180 bottom
R24 "ERJ-2GE0R00X" 0402 2930,2935 r0 top
R25 "ERJ-2GE0R00X" 0402 2930,2975 r0 top
R26 "ERJ-2GE0R00X" 0402 3086.81,3164.06 r270 top
R27 "ERJ-2GE0R00X" 0402 3126.81,3164.06 r270 top
R29 "ERJ-2GE0R00X" 0402 2195,0 r180 top
R30 "ERJ-2GE0R00X" 0402 2195,-40 r180 top
R31 "ERJ-2GE0R00X" 0402 1980,220 r270 top
R32 "ERJ-2GE0R00X" 0402 1935,220 r270 top
R33 "ERJ-2GE0R00X" 0402 1895,220 r270 top
R34 "ERJ-2GE0R00X" 0402 1855,220 r270 top
R35 "ERJ-2GE0R00X" 0402 1815,220 r270 top
R36 "ERJ-2GE0R00X" 0402 1775,220 r270 top
R40 "RT0603BRD07215KL" 0603 2500.15,3656.89 r180 top
R41 "RG1608P-2322-B-T5" 0603 2440.15,3526.89 r180 top
R42 "RG1608P-1651-B-T5" 0603 2545,3495 r90 top
R43 "RG1608P-3092-B-T5" 0603 2835,3168.05 r90 bottom
R44 "RT0603BRD072K15L" 0603 2835,3043.05 r90 bottom
R45 "RT0603BRD0752K3L" 0603 2682.93,3741.89 r270 top
R46 "RC0603JR-07330RL" 0603 2200,90 r180 top
R47 "RT0603BRD0718KL" 0603 2475,2675 r0 top
R50 "RG1608P-203-B-T5" 0603 2756.17,3473.35 r90 bottom
R64 "CRCW060310K0FKEA" 0603 4462.34,2617.19 r90 bottom
R65 "ERJ-2GE0R00X" 0402 3973.08,2922.19 r0 top
R66 "ERJ-2GE0R00X" 0402 3973.08,2877.19 r0 top
R67 "ERJ-2GE0R00X" 0402 3973.08,2832.19 r0 top
R68 "ERJ-2GE0R00X" 0402 3973.08,2787.19 r0 top
R69 "ERJ-2GE0R00X" 0402 3973.08,2742.19 r0 top
R70 "ERJ-2GE0R00X" 0402 3973.08,2697.19 r0 top
R71 "ERJ-2GE0R00X" 0402 3973.08,2652.19 r0 top
R72 "ERJ-2GE0R00X" 0402 3973.08,2607.19 r0 top
R73 "ERJ-2GE0R00X" 0402 3973.08,2562.19 r0 top
R74 "ERJ-2GE0R00X" 0402 3973.08,2517.19 r0 top
R75 "ERJ-2GE0R00X" 0402 3973.08,2472.19 r0 top
R76 "ERJ-2GE0R00X" 0402 3959.99,1286.32 r0 top
R77 "ERJ-2GE0R00X" 0402 3959.99,1241.32 r0 top
R78 "ERJ-2GE0R00X" 0402 3959.99,1196.32 r0 top
R79 "ERJ-2GE0R00X" 0402 3959.99,1151.32 r0 top
R80 "ERJ-2GE0R00X" 0402 3959.99,1106.32 r0 top
R81 "ERJ-2GE0R00X" 0402 3959.99,1061.32 r0 top
R82 "ERJ-2GE0R00X" 0402 3959.99,1016.32 r0 top
R83 "ERJ-2GE0R00X" 0402 3959.99,971.32 r0 top
R84 "ERJ-2GE0R00X" 0402 3959.99,926.32 r0 top
R85 "ERJ-2GE0R00X" 0402 3959.99,881.32 r0 top
R86 "ERJ-2GE0R00X" 0402 3959.99,836.32 r0 top
R87 "CRCW060310K0FKEA" 0603 4450,936.32 r90 bottom
R88 "CRCW04024K70JNED" 0402 3020,1460 r90 top
R89 "CRCW04024K70JNED" 0402 3065,1460 r90 top
R90 "CRCW04024K70JNED" 0402 3140,1535 r180 top
R91 "CRCW04024K70JNED" 0402 3045,1535 r0 top
R92 "CRCW0402100RJNED" 0402 3100,1915 r0 top
R95 "CRCW040233R0JNED" 0402 3325,2145 r0 top
R97 "RG1608P-102-B-T5" 0603 690,1850 r0 top
R98 "RG1608P-102-B-T5" 0603 690,2650 r0 top
R99 "CRCW0603249RFKEA" 0603 1330,2200 r270 top
R100 "RC0603FR-07499RL" 0603 1775,2195 r90 top
R101 "RC0603FR-07499RL" 0603 1775,2325 r270 top
R103 "RT0603BRD0710RL" 0603 1865,2225 r0 top
R104 "RT0603BRD0710RL" 0603 1865,2295 r0 top
R107 "RG1608P-102-B-T5" 0603 690,650 r0 top
R108 "RG1608P-102-B-T5" 0603 690,1450 r0 top
R110 "RG1608P-202-B-T5" 0603 1230,850 r0 bottom
R111 "RG1608P-202-B-T5" 0603 1110,850 r0 bottom
R112 "RC0603FR-0730RL" 0603 1295,1320 r180 top
R113 "RC0603FR-0730RL" 0603 1295,1015 r180 top
R114 "RC0603FR-07499RL" 0603 1415,1015 r0 top
R115 "RT0603BRD0710RL" 0603 1535,960 r0 top
R116 "RC0603FR-07499RL" 0603 1415,1320 r0 top
R117 "RT0603BRD0710RL" 0603 1535,1265 r0 top
R211 "ERJ-2GE0R00X" 0402 1635,2235 r0 top
R212 "ERJ-2GE0R00X" 0402 1635,2285 r0 top
R213 "ERJ-2GE0R00X" 0402 1230,905 r0 bottom
R214 "RG1608P-4990-B-T5" 0603 1280,1627.63 r0 top
R215 "RG1608P-4990-B-T5" 0603 1185,1652.63 r270 top
R216 "RG1608P-203-B-T5" 0603 1090,1627.63 r0 top
R217 "RG1608P-4992-B-T5" 0603 1240,1797.63 r90 top
R218 "RG1608P-4992-B-T5" 0603 1295,1797.63 r270 top
R219 "ERJ-3GEY0R00V" 0603 350,1850 r0 top
R220 "ERJ-3GEY0R00V" 0603 350,2650 r0 top
R221 "ERJ-3GEY0R00V" 0603 350,650 r0 top
R222 "ERJ-3GEY0R00V" 0603 350,1450 r0 top
R223 "ERJ-2GE0R00X" 0402 2135,915 r0 top
R225 "ERJ-2GE0R00X" 0402 2135,1000 r0 top
R226 "ERJ-2GE0R00X" 0402 2135,1040 r0 top
R232 "ERJ-2GE0R00X" 0402 2430,2105 r0 bottom
R233 "ERJ-2GE0R00X" 0402 2430,2150 r0 bottom
R234 "ERJ-2GE0R00X" 0402 2430,2195 r0 bottom
R235 "ERJ-2GE0R00X" 0402 2430,2240 r0 bottom
R240 "ERJ-2GE0R00X" 0402 2135,955 r0 top
R246 "RG1608P-4992-B-T5" 0603 3005,3475 r90 top
R247 "RG1608P-4992-B-T5" 0603 2419.93,3135 r270 top
R248 "ERJ-2GE0R00X" 0402 1540,2400 r0 top
R250 "ERJ-2GE0R00X" 0402 1455,880 r90 bottom
R252 "ERJ-2GE0R00X" 0402 1454.48,1189.27 r90 bottom
R255 "ERJ-2GE0R00X" 0402 2085,1615.41 r180 top
R256 "CRCW040233R0JNED" 0402 3325,2095 r0 top
R257 "CRCW040233R0JNED" 0402 3325,2040 r0 top
R258 "RG1608P-103-B-T5" 0603 2185,2560 r0 top
R259 "ERJ-2GE0R00X" 0402 2190,2610 r0 top
R260 "ERJ-2GE0R00X" 0402 2190,2655 r0 top
R261 "RG1608P-103-B-T5" 0603 1945,1425 r0 top
R262 "ERJ-2GE0R00X" 0402 1950,1475 r180 top
R263 "ERJ-2GE0R00X" 0402 1950,1520 r180 top
R268 "CRCW06031R00FKEA" 0603 1995,2460 r90 top
R269 "CRCW06031R00FKEA" 0603 1770,1305 r90 top
R270 "RG1608P-102-B-T5" 0603 600,1750 r0 top
R271 "RG1608P-102-B-T5" 0603 440,2750 r180 top
R278 "CRCW040233R0JNED" 0402 3325,1990 r0 top
R279 "ERJ-2GE0R00X" 0402 4357.34,2572.19 r0 bottom
R280 "ERJ-2GE0R00X" 0402 4359.99,901.32 r0 bottom
R284 "ERJ-2GE0R00X" 0402 1975,2375 r0 top
R288 "ERJ-2GE0R00X" 0402 1750,1220 r0 top
RDN1 "RG1608P-202-B-T5" 0603 1180,2410 r0 top
RDN2 "RG1608P-202-B-T5" 0603 1300,2410 r0 top
RDN3 "RG1608P-202-B-T5" 0603 1174.69,1210 r0 top
RDN4 "RG1608P-202-B-T5" 0603 1294.69,1210 r0 top
RDP1 "RG1608P-202-B-T5" 0603 1180,2110 r0 top
RDP2 "RG1608P-202-B-T5" 0603 1300,2110 r0 top
RDP3 "RG1608P-202-B-T5" 0603 1175,905 r0 top
RDP4 "RG1608P-202-B-T5" 0603 1295,905 r0 top
Renb "CRCW080520K5FKEA" 0805_HV 1870,3585 r180 bottom
Renb2 "RG1608P-3571-B-T5" 0603 3834.76,3600 r180 bottom
Renb3 "RG1608P-3571-B-T5" 0603 1645,515 r180 bottom
Rent "RT0805BRD07118KL" 0805_HV 1715,3585 r180 bottom
Rent2 "RT0603BRD0768K1L" 0603 3714.76,3600 r180 bottom
Rent3 "RT0603BRD0768K1L" 0603 1525,515 r180 bottom
Rfbb "RG1608P-152-B-T5" 0603 1765,3140 r180 bottom
Rfbb3 "RT0805BRD071K07L" 0805_HV 1620,145 r180 bottom
Rfbb5 "RT0805BRD071K07L" 0805_HV 3800.76,3282.2 r180 bottom
Rfbt "RT0603BRD0734KL" 0603 1640,3140 r180 bottom
Rfbt2 "CPF0603B6K34E" 0603 3660.76,3282.2 r180 bottom
Rfbt3 "RG1608P-4021-B-T5" 0603 1480,145 r180 bottom
Ron "RT0603BRD07383KL" 0603 1670,3480 r90 bottom
Ron2 "RT0603BRD07113KL" 0603 3624.76,3565 r90 bottom
Ron3 "RT0603BRD0778K7L" 0603 1435,480 r90 bottom
TP1 "Pogo Pad" PogoPad 2460,2430 r0 top
TP2 "Pogo Pad" PogoPad 3185,2460.3 r0 top
TP3 "5015" Testpoint_Keystone_Miniature 2440,2975 r0 top
TP4 "Pogo Pad" PogoPad 2780,1111.53 r0 top
TP7 "Pogo Pad" PogoPad 2927.81,2243.8 r0 top
TP8 "5015" Testpoint_Keystone_Miniature 1645,1885 r180 top
TP11 "5015" Testpoint_Keystone_Miniature 2120,172.13 r0 top
TP16 "Pogo Pad" PogoPad 3445,2215 r0 top
TP17 "5015" Testpoint_Keystone_Miniature 915,3200 r180 top
TP25 "5015" Testpoint_Keystone_Miniature 2530.38,3235 r270 top
TP26 "5015" Testpoint_Keystone_Miniature 2890,3343.05 r180 top
Tp27 "5015" Testpoint_Keystone_Miniature 2307.25,742.23 r0 top
TP28 "5015" Testpoint_Keystone_Miniature 1240,1915.26 r0 top
TP29 "5015" Testpoint_Keystone_Miniature 1240,1527.63 r0 top
TP30 "5015" Testpoint_Keystone_Miniature 1175,765 r180 bottom
TP31 "Pogo Pad" PogoPad 3445,2115 r0 top
TP32 "Pogo Pad" PogoPad 3445,2015 r0 top
TP33 "Pogo Pad" PogoPad 3445,1915 r0 top
TP34 "Pogo Pad" PogoPad 2780,1385 r90 top
TP35 "Pogo Pad" PogoPad 2520.3,1111.53 r90 top
TP_3P8V "5015" Testpoint_Keystone_Miniature 1645,45 r90 top
TP_5P5V "5015" Testpoint_Keystone_Miniature 3650,3035.76 r0 top
TP_18P5V "5015" Testpoint_Keystone_Miniature 1660,2923.54 r270 top
TPAGND1 "5015" Testpoint_Keystone_Miniature 370,2250 r90 top
TPAGND2 "5015" Testpoint_Keystone_Miniature 365,1045 r90 top
TPAGND3 "5015" Testpoint_Keystone_Miniature 800,1680 r270 top
TPAGND4 "5015" Testpoint_Keystone_Miniature 470,1045 r90 top
TPGND1 "5015" Testpoint_Keystone_Miniature 3765,375 r90 top
TPGND2 "5015" Testpoint_Keystone_Miniature 2510,1725 r90 top
TPGND3 "5015" Testpoint_Keystone_Miniature 3814.99,1701.32 r90 top
TPGND4 "5015" Testpoint_Keystone_Miniature 3600,690 r90 top
U1 "OPA625IDBVR" DBV0006A_N 1415,840 r270 top
U2 "OPA625IDBVR" DBV0006A_N 1415,1145 r270 top
U3 "REF6041IDGKR" DGK0008A_N 1780,1680.41 r0 top
U4 "OPA376AIDBVR" DBV0005A_N 1055,1780.26 r180 top
U5 "LMZ14202TZX-ADJ/NOPB" TZA07A_V 1140,335 r180 bottom
U6 "TPS7A4700RGWR" RGW0020A 1905,105 r180 bottom
U7 "TPS7A4700RGWR" RGW0020A 3125,2900 r90 bottom
U8 "TPS7A4700RGWR" RGW0020A 1960,2960 r180 bottom
U9 "LM5574MT" MTC16_N 2577.87,3646.89 r180 bottom
U10 "LM7705MM/NOPB" MUA08A_N 2636.33,462.23 r90 bottom
U11 "TPS7A3001MDGNTEP" DGN0008D_N 2675,3123.05 r180 bottom
U13 "BR24G32FVT-3AGE2" TSOP65P640X120-8N 4267.34,2672.19 r180 bottom
U14 "BR24G32FVT-3AGE2" TSOP65P640X120-8N 4264.99,1001.32 r180 bottom
U15 "LMK61E2-SIAR" SIA0008B 3050,1675 r90 top
U18 "SN74AUP1G80DCKR" DCK0005A_N 3157.81,2323.8 r270 top
U19 "SN74AHC1G04DBVR" DBV0005A_N 2927.81,2373.8 r90 top
U22 "LMZ14201TZX-ADJ/NOPB" TZA07A_V 1360,3355 r180 bottom
U23 "LMZ14203TZ-ADJ/NOPB" TZA07A_V 3329.76,3435 r180 bottom
U31 "SN74AUP1G80DCKR" DCK0005A_N 2775.21,1230 r270 top
U32 "SN74AHC1G04DBVR" DBV0005A_N 2519.83,1241.53 r90 top
U33 "LMK00804BPW" PW0016A_N 3110,2055 r0 top
UADS1 "ADS8910BIRGER" RGE0024H 2120,2260 r270 top
UADS2 "ADS8910BIRGER" RGE0024H 1895,1110 r270 top
ZZ2 "These assemblies are ESD sensitive, ESD precautions shall be observed." AssemblyNote 2000,3305 r90 top
ZZ3 "These assemblies must be clean and free from flux and all contaminants. Use of no clean flux is not acceptable." AssemblyNote 2100,3305 r90 top
ZZ4 "These assemblies must comply with workmanship standards IPC-A-610 Class 2, unless otherwise specified." AssemblyNote 2200,3305 r90 top

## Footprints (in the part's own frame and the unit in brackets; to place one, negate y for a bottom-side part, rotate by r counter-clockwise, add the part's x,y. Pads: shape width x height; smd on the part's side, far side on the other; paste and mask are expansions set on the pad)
0402 [mm] "0402 from SM-752 data"
  rect 0.8x0.6 smd: 1(-0.6,0) 2(0.6,0)
  silkscreen extent -1.22,-0.52 1.22,0.52, body extent -0.55,-0.3 0.55,0.3, height 0.6
0603 [mm] "0603 from SM-752 data"
  rect 1x0.95 smd: 1(-0.8,0) 2(0.8,0)
  silkscreen extent -1.52,-0.69 1.52,0.69, body extent -0.87,-0.47 0.87,0.47, height 1
0603_120 [mm] "0603_120"
  rect 1x1 smd: 1(-0.8,0) 2(0.8,0)
  silkscreen extent -0.1,-0.58 0.1,0.58, body extent -0.87,-0.48 0.87,0.48, height 1.2
0805 [mm] "0805 from SM-752 data"
  rect 1.3x1.5 smd: 1(-0.85,0) 2(0.85,0)
  silkscreen extent -1.72,-0.97 1.72,0.97, body extent -1.1,-0.72 1.1,0.72, height 1.45
0805_HV [mil] "0805 with 30mil clearance between pads"
  rect 50x63 smd: 1(-40,0) 2(40,0)
  silkscreen extent -74,-40 74,40, body extent -43,-29 43,29, height 57
1206_190 [mm] "1206_190"
  rect 1.1x1.6 smd: 1(-1.7,0) 2(1.7,0)
  silkscreen extent -0.9,-1 0.9,1, body extent -1.75,-0.95 1.75,0.95, height 1.9
1210_270 [mm] "1210"
  rect 1.3x2.7 smd: 1(-1.45,0) 2(1.45,0)
  silkscreen extent -2.32,-1.57 2.32,1.57, body extent -1.7,-1.35 1.7,1.35, height 2.7
1210_280 [mm] "SMD, 2-Leads, Body 3.6x2.8mm, Height 2.8mm"
  rect 1.1x2.2 smd: 1(-1.65,0) 2(1.65,0)
  silkscreen extent -0.84,-1.4 0.84,1.4, body extent -1.8,-1.4 1.8,1.4, height 2.8
6032-28 [mm] "Medium Density IPC based on Vishay Sprague 293D datasheet."
  rect 2.55x2.3 smd: 1(-2.375,0) 2(2.375,0)
  silkscreen extent -3.96,-1.75 3.2,1.83, body extent -3.15,-1.75 3.15,1.75, height 2.8
AssemblyNote [mil] "Assembly Note"
D0008A_N [mm] "SOIC, 8-Leads, Body 4.9x3.9mm, Pitch 1.27mm, IPC Medium Density"
  oval 1.45x0.6 smd: 1(-2.725,1.905) 2(-2.725,0.635) 3(-2.725,-0.635) 4(-2.725,-1.905) 5(2.725,-1.905) 6(2.725,-0.635) 7(2.725,0.635) 8(2.725,1.905)
  silkscreen extent -3.3,-2.5 0.9,2.5, body extent -3,-2.45 3,2.45, height 1.63
DBV0005A_N [mm] "SOT23, 5-Leads, Body 2.9x1.6mm, Pitch 0.95mm, Lead Span 2.8mm, IPC Medium Density"
  rrect17% 1x0.6 smd: 1(-1.375,0.95) 2(-1.375,0) 3(-1.375,-0.95) 4(1.375,-0.95) 5(1.375,0.95)
  silkscreen extent -1.63,-1.55 0.38,1.55, body extent -1.42,-1.46 1.42,1.46, height 1.09
DBV0006A_N [mm] "SOT23, 6-Leads, Body 2.9x1.6mm, Pitch 0.95mm, Lead Span 2.8mm, IPC Medium Density"
  rrect17% 1x0.6 smd: 1(-1.375,0.95) 2(-1.375,0) 3(-1.375,-0.95) 4(1.375,-0.95) 5(1.375,0) 6(1.375,0.95)
  silkscreen extent -1.68,-1.55 0.5,1.55, body extent -1.42,-1.46 1.42,1.46, height 1.12
DCK0005A_N [mm] "SOT353, 5-Leads, Body 2x1.3mm, Pitch 0.65mm, Lead Span 2.1mm, IPC Medium Density"
  rrect25% 0.85x0.4 smd: 1(-1.125,0.65) 2(-1.125,0) 3(-1.125,-0.65) 4(1.125,-0.65) 5(1.125,0.65)
  silkscreen extent -1.48,-1.02 0.55,1.1, body extent -1.14,-1 1.14,1, height 0.95
DGK0008A_N [mm] "TSOP, 8-Leads, Body 3x3mm, Pitch 0.65mm, IPC Medium Density"
  oval 1.35x0.45 smd: 1(-2.225,0.975) 2(-2.225,0.325) 3(-2.225,-0.325) 4(-2.225,-0.975) 5(2.225,-0.975) 6(2.225,-0.325) 7(2.225,0.325) 8(2.225,0.975)
  silkscreen extent -2.75,-1.55 0.95,1.55, body extent -2.45,-1.5 2.45,1.5, height 0.96
DGN0008D_N [mm] "TSOP, 8-Leads, Body 3x3mm, Pitch 0.65mm, Thermal Pad 1.89x1.57mm, IPC Medium Density"
  rrect100% 1.35x0.45 smd: 1(-2.225,0.975) 2(-2.225,0.325) 3(-2.225,-0.325) 4(-2.225,-0.975) 5(2.225,-0.975) 6(2.225,-0.325) 7(2.225,0.325) 8(2.225,0.975)
  rrect6% 1.57x1.89 smd: 9(0,0)
  silkscreen extent -2.73,-1.55 0.95,1.55, body extent -2.46,-1.5 2.46,1.5, height 1.1
DR73 [mm]
  rect 2.5x3.25 smd: 1(-3,0) 2(3,0)
  silkscreen extent -4.75,-3.8 4.75,3.8, body extent -3.8,-3.8 3.8,3.8, height 3.55
Fiducial10-20#1 [mm]
  round 1 smd mask+0.5: 1(0,0)
Fiducial10-20#2 [mm]
  round 1 smd mask+0.5: 1(0,0)
  Layer 1 - Top Layer keep-out circle w1.178: c0,0 r0.5
JOHNSON_142-0701-801 [mil] "Johnson Components recommended land pattern"
  rect 90x200 smd: 1(0,0)
  round 38 hole 18: 2(-172.5,-135) 3(172.5,-135)
  rect 95x200 smd: 2(-172.5,0) 3(172.5,0)
  rect 95x200 smd far side: 4(-172.5,0) 5(172.5,0)
  Layer 1 - Top Layer lines w18: -172.5,0 -172.5,-135 ; 172.5,0 172.5,-135
  Layer 4 - Bottom Layer lines w18: -172.5,0 -172.5,-135 ; 172.5,0 172.5,-135
  silkscreen extent -235,-170 235,100, body extent -190,-92 190,480, height 165
Keystone_1902C [mil] "Hex Standoff, 4-40 threaded, nylon"
  body extent -145,-126 146,126, height 501
Molex_87898-0204 [mm] "Header, 2.54 mm, 2x1, R/A, SMT"
  rect 1.27x2.96 smd: 1(-1.27,1.8) 2(1.27,-1.8)
  silkscreen extent -2.54,-1.27 2.54,1.27, body extent -2.54,-2.4 2.54,2.4, height 9.65
MTC16_N [mm] "TSOP, 16-Leads, Body 5x4.4mm, Pitch 0.65mm, IPC Medium Density"
  oval 1.7x0.35 smd: 1(-2.85,2.275) 2(-2.85,1.625) 3(-2.85,0.975) 4(-2.85,0.325) 5(-2.85,-0.325) 6(-2.85,-0.975) 7(-2.85,-1.625) 8(-2.85,-2.275) 9(2.85,-2.275) 10(2.85,-1.625) 11(2.85,-0.975) 12(2.85,-0.325) 13(2.85,0.325) 14(2.85,0.975) 15(2.85,1.625) 16(2.85,2.275)
  silkscreen extent -3.97,-2.55 1.6,3.12, body extent -2.25,-2.55 2.25,2.55, height 1.1
MUA08A_N [mm] "TSOP, 8-Leads, Body 3x3mm, Pitch 0.65mm, IPC Medium Density"
  oval 1.7x0.45 smd: 1(-2.1,0.975) 2(-2.1,0.325) 3(-2.1,-0.325) 4(-2.1,-0.975) 5(2.1,-0.975) 6(2.1,-0.325) 7(2.1,0.325) 8(2.1,0.975)
  silkscreen extent -2.22,-1.55 0.85,1.88, body extent -1.6,-1.6 1.6,1.6, height 1.09
Net-Tie_50milWide_30milLong [mil] "50mil net tie, no solder mask opening, no solder paste"
  rect 30x100 on Mid1 paste-20 mask-20: 1(-15,0) 2(15,0)
"NY PMS 440 0025 PH" [mm] "4-40 nylon screw and mounting hole"
  round 8 hole 3.2: 1(0,0)
  body extent -3.3,-3.3 3.3,3.3, height 2.69
Pb-Free_Overlay_Small [mil]
  silkscreen extent -46,-46 46,46
PogoPad [mil] "No Solder Paste"
  round 70 smd paste-35: 1(0,0)
PowerDI123 [mm] "Diodes Inc recommended land pattern, document number DS30628 Rev. 6-2"
  rect 2.2x1.4 smd: 1(-1.275,0)
  rect 0.9x1.4 smd: 2(1.275,0)
  silkscreen extent -3.1,-1.09 1.76,1.09, body extent -2.37,-0.96 1.53,0.97, height 1
PW0016A_N [mm] "TSOP, 16-Leads, Body 5x4.4mm, Pitch 0.65mm, IPC Medium Density"
  oval 1.4x0.45 smd: 1(-2.95,2.275) 2(-2.95,1.625) 3(-2.95,0.975) 4(-2.95,0.325) 5(-2.95,-0.325) 6(-2.95,-0.975) 7(-2.95,-1.625) 8(-2.95,-2.275) 9(2.95,-2.275) 10(2.95,-1.625) 11(2.95,-0.975) 12(2.95,-0.325) 13(2.95,0.325) 14(2.95,0.975) 15(2.95,1.625) 16(2.95,2.275)
  silkscreen extent -3.5,-2.55 1.85,2.75, body extent -3.21,-2.5 3.21,2.5, height 1
RGE0024H [mm] "QFN, 24-Leads, Body 4x4mm, Pitch 0.5mm, Thermal Pad 2.7x2.7mm, TI Recommended"
  rrect40% 0.6x0.25 smd: 1(-1.9,1.25) 2(-1.9,0.75) 3(-1.9,0.25) 4(-1.9,-0.25) 5(-1.9,-0.75) 6(-1.9,-1.25) 13(1.9,-1.25) 14(1.9,-0.75) 15(1.9,-0.25) 16(1.9,0.25) 17(1.9,0.75) 18(1.9,1.25)
  rrect40% 0.25x0.6 smd: 7(-1.25,-1.9) 8(-0.75,-1.9) 9(-0.25,-1.9) 10(0.25,-1.9) 11(0.75,-1.9) 12(1.25,-1.9) 19(1.25,1.9) 20(0.75,1.9) 21(0.25,1.9) 22(-0.25,1.9) 23(-0.75,1.9) 24(-1.25,1.9)
  rrect4% 2.7x2.7 smd paste-1.35: 25(0,0)
  silkscreen extent -2.22,-2.22 2.22,2.22, body extent -2.07,-2.07 2.07,2.07, height 1.01
RGT0016A [mm] "QFN, 16-Leads, Body 3x3mm, Pitch 0.5mm, Thermal Pad 1.45x1.45mm, TI Recommended"
  rrect42% 0.6x0.24 smd: 1(-1.4,0.75) 2(-1.4,0.25) 3(-1.4,-0.25) 4(-1.4,-0.75) 9(1.4,-0.75) 10(1.4,-0.25) 11(1.4,0.25) 12(1.4,0.75)
  rrect42% 0.24x0.6 smd: 5(-0.75,-1.4) 6(-0.25,-1.4) 7(0.25,-1.4) 8(0.75,-1.4) 13(0.75,1.4) 14(0.25,1.4) 15(-0.25,1.4) 16(-0.75,1.4)
  rrect7% 1.45x1.45 smd paste-0.725: 17(0,0)
  silkscreen extent -1.72,-1.73 1.72,1.73, body extent -1.57,-1.57 1.58,1.58, height 1.01
RGW0020A [mm] "QFN, 20-Leads, Body 5x5mm, Pitch 0.65mm, Thermal Pad 3.15x3.15mm, TI Recommended"
  oval 0.75x0.3 smd: 1(-2.325,1.3) 2(-2.325,0.65) 3(-2.325,0) 4(-2.325,-0.65) 5(-2.325,-1.3) 11(2.325,-1.3) 12(2.325,-0.65) 13(2.325,0) 14(2.325,0.65) 15(2.325,1.3)
  oval 0.3x0.75 smd: 6(-1.3,-2.325) 7(-0.65,-2.325) 8(0,-2.325) 9(0.65,-2.325) 10(1.3,-2.325) 16(1.3,2.325) 17(0.65,2.325) 18(0,2.325) 19(-0.65,2.325) 20(-1.3,2.325)
  rect 3.15x3.15 smd paste-1.575: 21(0,0)
  silkscreen extent -2.73,-2.73 2.73,2.73, body extent -2.58,-2.57 2.57,2.58, height 1.01
Samtec_QTH-030-01-x-D-A [mil] "Header (Shrouded), 19.7mil, 30x2, SMT"
  rect 12x57 smd mask+1: 1(-285.7,121.5) 2(-285.7,-121.5) 3(-266,121.5) 4(-266,-121.5) 5(-246.3,121.5) 6(-246.3,-121.5) 7(-226.6,121.5) 8(-226.6,-121.5) 9(-206.9,121.5) 10(-206.9,-121.5) 11(-187.2,121.5) 12(-187.2,-121.5) 13(-167.5,121.5) 14(-167.5,-121.5) 15(-147.8,121.5) 16(-147.8,-121.5) 17(-128.1,121.5) 18(-128.1,-121.5) 19(-108.4,121.5) 20(-108.4,-121.5) 21(-88.7,121.5) 22(-88.7,-121.5) 23(-69,121.5) 24(-69,-121.5) 25(-49.3,121.5) 26(-49.3,-121.5) 27(-29.6,121.5) 28(-29.6,-121.5) 29(-9.9,121.5) 30(-9.9,-121.5) 31(9.8,121.5) 32(9.8,-121.5) 33(29.5,121.5) 34(29.5,-121.5) 35(49.2,121.5) 36(49.2,-121.5) 37(68.9,121.5) 38(68.9,-121.5) 39(88.6,121.5) 40(88.6,-121.5) 41(108.3,121.5) 42(108.3,-121.5) 43(128,121.5) 44(128,-121.5) 45(147.7,121.5) 46(147.7,-121.5) 47(167.4,121.5) 48(167.4,-121.5) 49(187.1,121.5) 50(187.1,-121.5) 51(206.8,121.5) 52(206.8,-121.5) 53(226.5,121.5) 54(226.5,-121.5) 55(246.2,121.5) 56(246.2,-121.5) 57(265.9,121.5) 58(265.9,-121.5) 59(285.6,121.5) 60(285.6,-121.5)
  round 0 hole 40 unplated mask+1: MH1(-364,80) MH2(364,80)
  rect 100x25 smd mask+1: MP1(-332.7,0) MP4(332.3,0)
  rect 185x25 smd mask+1: MP2(-125.2,0) MP3(124.8,0)
  silkscreen extent -394,-118 394,131, body extent -394,-140 394,140, height 170
Samtec_TMM-103-01-x-S-SM [mm] "Header,2mm, 3x1, SMT"
  rect 1.02x3.56 smd: 1(-2,1.015) 2(0,-1.015) 3(2,1.015)
  silkscreen extent -3.2,-0.99 3,0.99, body extent -3,-2.41 3,2.41, height 5.97
SIA0008B [mm] "SIP 8-Leads, Body 5x7mm"
  rrect17% 1x0.6 on Top Paste: 1(-1.85,2.14) 1(-1.85,2.94) 2(-1.85,-0.4) 2(-1.85,0.4) 3(-1.85,-2.94) 3(-1.85,-2.14) 4(1.85,-2.94) 4(1.85,-2.14) 5(1.85,-0.4) 5(1.85,0.4) 6(1.85,2.14) 6(1.85,2.94)
  rrect10% 1x1.4 smd paste-0.5: 1(-1.85,2.54) 2(-1.85,0) 3(-1.85,-2.54) 4(1.85,-2.54) 5(1.85,0) 6(1.85,2.54)
  rrect12% 0.8x0.8 smd: 7(0,2.865) 8(0,-2.865)
  silkscreen extent -2.64,-3.63 2.64,3.63, body extent -2.56,-3.56 2.56,3.56, height 1.13
SMC [mm] "DO-214-AB/SMC; 2 C-Bend Leads; Body 7.9 x 5.9 mm, inc. leads (LxW)"
  rect 2.4x3.3 smd: 1(3.475,0) 2(-3.475,0)
  silkscreen extent -5.43,-2.05 5.07,2.05
Testpoint_Keystone_Miniature [mil] "Miniature SMT test point"
  rect 135x70 smd: 1(0,0)
  silkscreen extent -78,-46 78,45, body extent -52,-20 52,20, height 61
TI_Stacked_Overlay_Small [mil]
  silkscreen extent -418,-98 418,98
TSOP65P640X120-8N [mm] "TSOP, 8-Leads, Body 3.1x4.5mm (max), Pitch 0.65mm, IPC Medium Density"
  oval 1.55x0.35 smd mask+0.08: 1(-2.875,0.975) 2(-2.875,0.325) 3(-2.875,-0.325) 4(-2.875,-0.975) 5(2.875,-0.975) 6(2.875,-0.325) 7(2.875,0.325) 8(2.875,0.975)
  silkscreen extent -1.7,-1.55 1.7,1.55, body extent -2.25,-1.55 2.25,1.55, height 1.21
TZA07A_V [mm] "D2-PAK, 8-Leads, Body 9.9x10.2mm, Pitch 1.27mm, Lead Span 13.8mm, NSC Recommended"
  rect 2.41x0.89 smd: 1(-5.35,3.81) 2(-5.35,2.54) 3(-5.35,1.27) 4(-5.35,0) 5(-5.35,-1.27) 6(-5.35,-2.54) 7(-5.35,-3.81)
  rect 8.54x5.35 smd: 8(2.28,0)
  silkscreen extent -5.48,-5.15 -2.7,5.15, body extent -2.55,-5.2 7.55,5.2, height 4.67
WL-SMCW_RED [mm] "WURTH"
  rect 0.8x0.8 smd: 1(-0.8,0) 2(0.8,0)
  silkscreen extent -1.9,-0.8 1.2,0.8, body extent -0.85,-0.45 0.85,0.45, height 0.8
WURTH_61300211121 [mm] "Header, 2.54mm, 2x1, TH"
  rect 1.65x1.65 hole 1.15: 1(-1.27,0)
  round 1.65 hole 1.15: 2(1.27,0)
  silkscreen extent -2.54,-1.27 2.54,1.6, body extent -2.54,-1.27 2.54,1.27, height 8.54
WURTH_61300311121 [mm] "Header, 2.54mm, 3x1, TH"
  rect 1.65x1.65 hole 1.15: 1(-2.54,0)
  round 1.65 hole 1.15: 2(0,0) 3(2.54,0)
  silkscreen extent -3.81,-1.27 3.81,1.6, body extent -3.81,-1.27 3.81,1.27, height 8.54
Wurth_691213710002 [mm] "TH, 2-Leads, Body 10x8.3mm, Pitch 5mm"
  rect 1.8x1.8 hole 1.3: 1(-2.5,0)
  round 1.8 hole 1.3: 2(2.5,0)
  silkscreen extent -5,-4.75 5,4.15, body extent -5.6,-4.15 5,4.15, height 10
Wurth_WA-SMSI [mm] "ROUND STANDOFF M3 STEEL 5MM"
  round 0 hole 4.4 unplated: ""(0,0)
  Layer 1 - Top Layer region: -3.711,0 -3.666,0.581 -3.53,1.147 -3.307,1.685 -3.003,2.182 -2.624,2.624 -2.182,3.003 -1.685,3.307 -1.147,3.53 -0.581,3.666 0,3.711 0.581,3.666 1.147,3.53 1.685,3.307 2.182,3.003 2.624,2.624 3.003,2.182 3.307,1.685 3.53,1.147 3.666,0.581 3.711,0 3.7,0 2.466,0 2.418,0.481 2.278,0.944 2.05,1.37 1.744,1.744 1.37,2.05 0.944,2.278 0.481,2.418 0,2.466 -0.481,2.418 -0.944,2.278 -1.37,2.05 -1.744,1.744 -2.05,1.37 -2.278,0.944 -2.418,0.481 -2.466,0 -2.454,0
  Layer 1 - Top Layer region: -3.711,0 -3.666,-0.581 -3.53,-1.147 -3.307,-1.685 -3.003,-2.182 -2.624,-2.624 -2.182,-3.003 -1.685,-3.307 -1.147,-3.53 -0.581,-3.666 0,-3.711 0.581,-3.666 1.147,-3.53 1.685,-3.307 2.182,-3.003 2.624,-2.624 3.003,-2.182 3.307,-1.685 3.53,-1.147 3.666,-0.581 3.711,0 3.7,0 2.466,0 2.418,-0.481 2.278,-0.944 2.05,-1.37 1.744,-1.744 1.37,-2.05 0.944,-2.278 0.481,-2.418 0,-2.466 -0.481,-2.418 -0.944,-2.278 -1.37,-2.05 -1.744,-1.744 -2.05,-1.37 -2.278,-0.944 -2.418,-0.481 -2.466,0 -2.454,0
  silkscreen extent -4.1,-4.1 4.1,4.1, body extent -3,-3 3,3, height 5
